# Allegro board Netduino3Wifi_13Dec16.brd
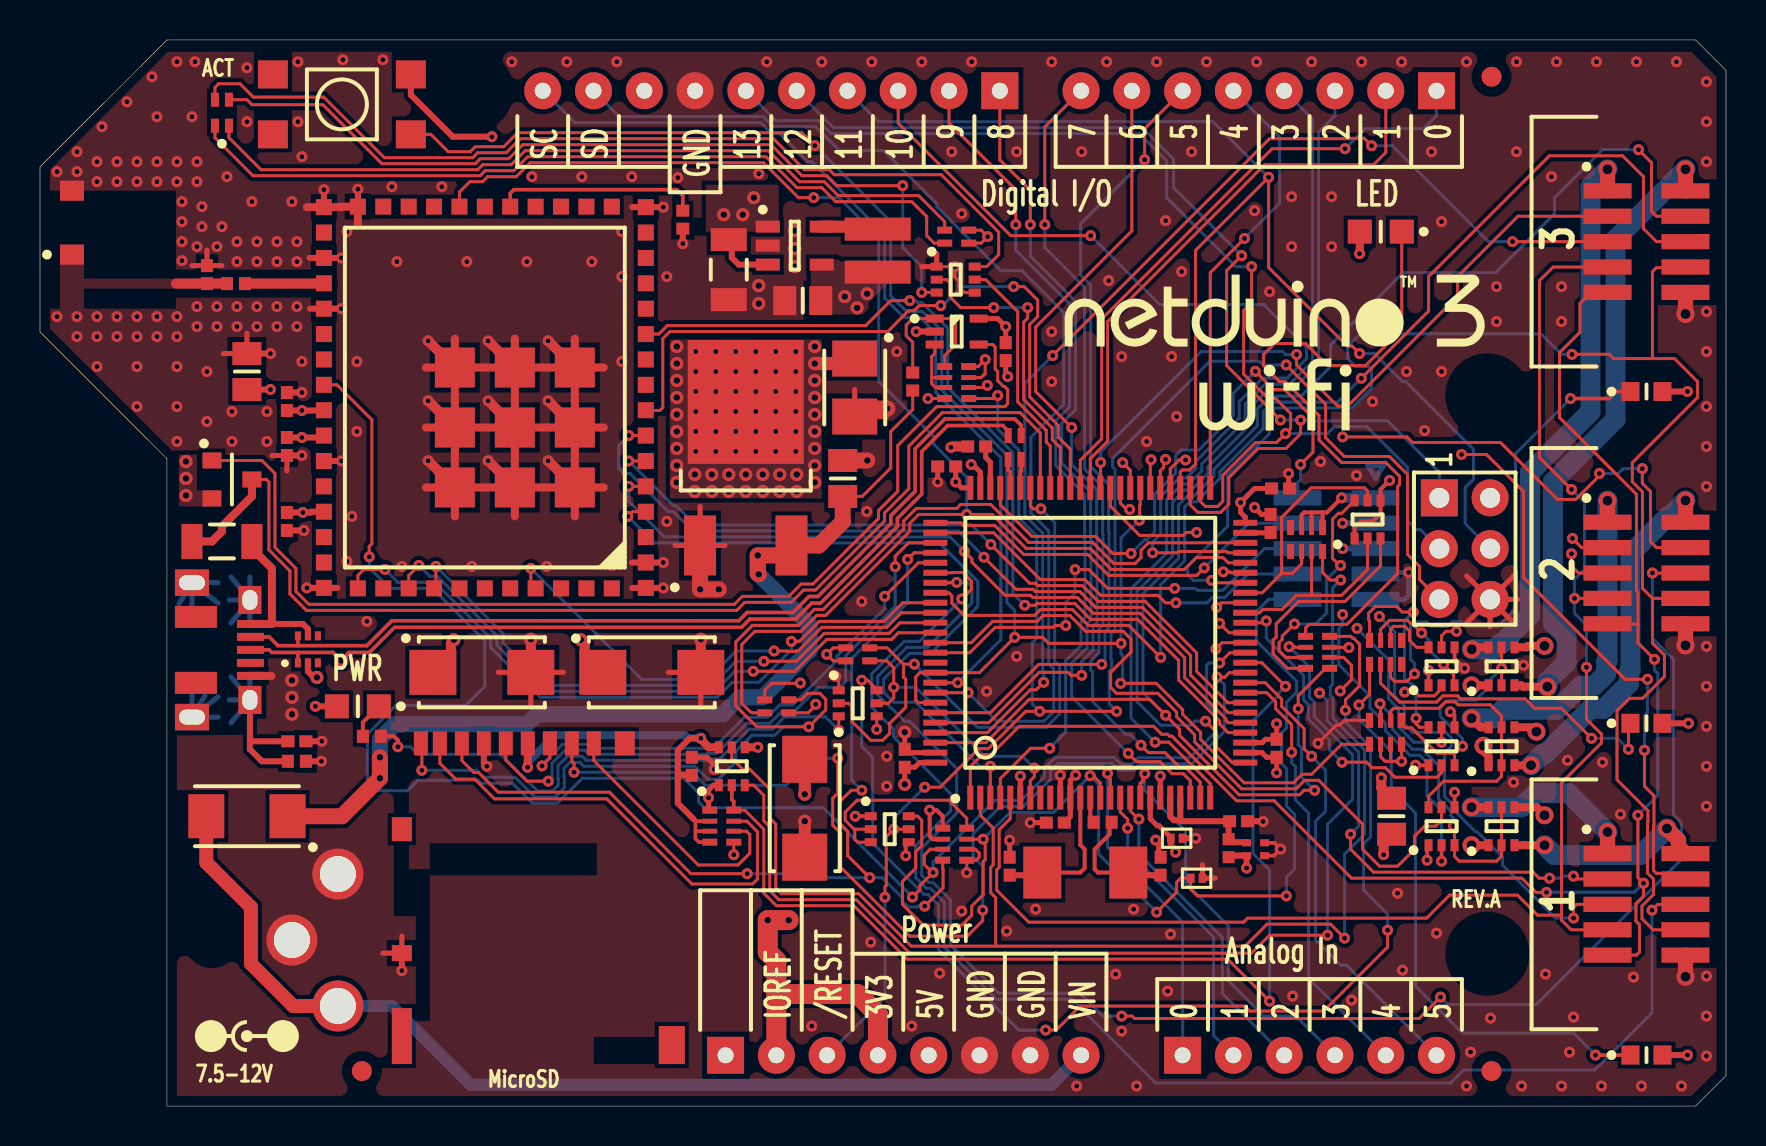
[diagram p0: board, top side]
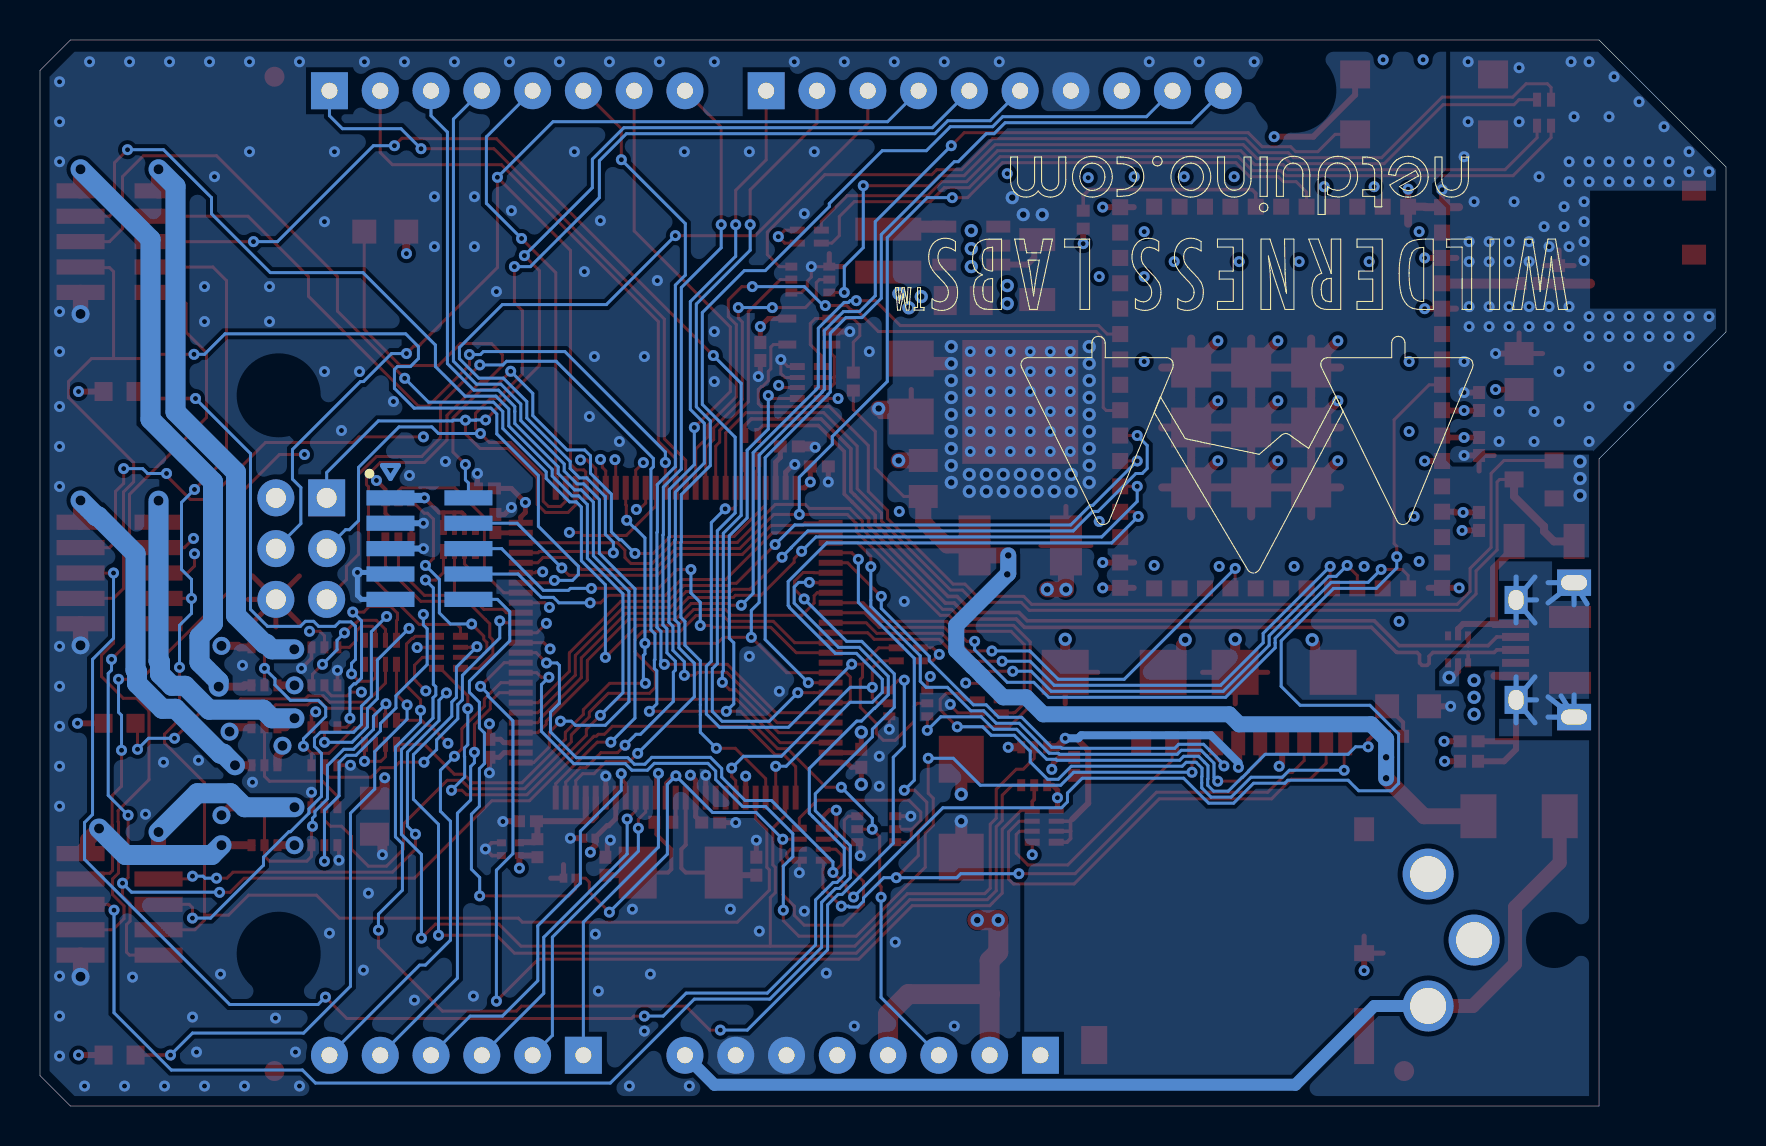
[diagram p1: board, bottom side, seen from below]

Outline 84.33 x 53.34 mm; copper layers: TOP, L2-GND, L3-PWR, BOTTOM. Coordinates in mm from the lower left corner of the outline.
Outline path: 0,46.99 0,38.73 6.35,32.38 6.35,0 82.8,0 84.33,1.52 84.33,51.82 82.8,53.34 6.35,53.34 0,46.99

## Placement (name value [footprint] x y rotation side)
C1  22uF  [CAPC3216X180N]  34.45 41.85 270 top
C2  10uF  [CAPC2012X125N]  40.15 31.4 90 top
C4  22uF  [CAPC2012X125N]  38.15 40.3 180 top
C5  0.1uF  [CAPC1005X55N]  59.95 14.25 0 top
C6  0.1uF  [CAPC1005X55N]  48.3 37.75 270 top
C7  1uF  [GNM1M2]  60.8 12.85 0 top
C9  0.1uF  [CAP-0201]  56.85 13.4 0 top
C10  0.1uF  [CAPC1005X55N]  50.78 14.18 180 top
C11  0.1uF  [CAPC1005X55N]  61.85 17.9 270 top
C12  0.1uF  [CAPC1005X55N]  62.05 30.9 0 top
C13  0.1uF  [CAPC1005X55N]  45.35 32 180 top
C14  0.1uF  [CAPC1005X55N]  43.25 17.4 90 top
C16  0.1uF  [CAPC1005X55N]  46.85 33 180 top
C17  2.2uF  [CAPC1005X55N]  61.55 29.15 90 top
C18  18pF  [CAPC1005X55N]  48.5 12 90 top
C19  18pF  [CAPC1005X55N]  56.05 12 90 top
C20  4.7nF  [CAPC1005X55N]  12.85 18.25 180 top
C21  100uF  [CAPMP6032X280N]  38.25 14.9 270 top
C22  0.1uF  [CAPC1005X55N]  32.6 17 90 top
C42  22uF  [CAPC2012X125N]  67.6 14.5 270 top
C43  47uF  [F931A476MBA]  40.75 35.95 270 top
C44  1pF  [CAPC1005X55N]  8.35 41.6 90 top
C47  22uF  [CAPC2012X125N]  10.35 36.75 90 top
C48  0.1uF  [CAPC1005X55N]  12.35 29.25 270 top
C49  0.1uF  [CAPC1005X55N]  12.35 35.25 90 top
C50  0.1uF  [CAPC1005X55N]  12.35 33 270 top
C51  100uF  [CAPMP6032X280N]  22.1 21.7 0 top
C52  100uF  [CAPMP6032X280N]  30.6 21.7 0 top
C53  0.1uF  [CAP-0201]  57.85 11.4 0 top
D1  WHITE  [LEDC2012X110N]  15.9 20 180 top
D2  BLUE  [LEDC2012X110N]  67.06 43.75 180 top
D3  SS15E-TP  [SS15-TP]  10.35 14.5 180 top
D4  -  [SP3003-04XTG]  13.4 22.85 90 top
D5  BLUE  [LEDC1608X80N]  80.35 2.55 0 top
D6  BLUE  [LEDC1608X80N]  80.35 19.15 0 top
D7  BLUE  [LEDC1608X80N]  80.35 35.75 0 top
D9  LTST-C295KGKSKT  [LTST-C295]  9.1 49.7 90 top
F1  MF-NSMF075-2  [RESC3216X100N]  9.1 28.25 180 top
F2  -  [FID_1-00_X_2-00]  16.1 1.75 0 top
F3  -  [FID_1-00_X_2-00]  72.6 1.75 0 top
F4  -  [FID_1-00_X_2-00]  72.6 51.5 0 top
J1  -  [ADC-043A-1]  14.9 8.31 90 top
J2  HDR100IMP08F-G-V-TH-BLUE  [HDR100IMP08F-G-V-TH]  69.85 50.8 180 top
J3  HDR100IMP08F-G-V-TH-BLUE  [HDR100IMP10F-G-V-TH]  48.01 50.8 180 top
J4  HDR100IMP08F-G-V-TH-BLUE  [HDR100IMP06F-G-V-TH]  57.15 2.54 0 top
J5  -  [DX4R005JJ2R1800]  6.35 22.82 270 top
J6  HDR100IMP08F-G-V-TH-BLUE  [HDR100IMP08F-G-V-TH]  34.29 2.54 0 top
J7  -  [67996-206HLF]  69.99 30.43 270 top
J8  -  [MINI_JTAG_SMD]  64.85 27.89 180 bottom
J9  DM3AT-SF-PEJM5  [DM3AT-SF-PEJ]  27.7 17.55 0 top
J10  HDR050IDC10MS2-G-V-SM-BLUE  [20021521-00010T1LF]  80.35 10.09 0 top
J11  HDR050IDC10MS2-G-V-SM-BLUE  [20021521-00010T1LF]  80.35 26.67 0 top
J12  HDR050IDC10MS2-G-V-SM-BLUE  [20021521-00010T1LF]  80.35 43.25 0 top
J13  2.45GHz Antenna  [AH316M245001-T]  1.6 44.2 90 top
L1  2.2uH  [LQH3NPN2R2NM0L]  41.9 42.8 270 top
L2  BEAD FERRITE/SM  [INDC1005X55N]  59.45 12.9 270 top
L3  3.6nH  [RESC1005X40AN]  9.8 41.15 180 top
MT1  -  [MTG320H420NP_720KO]  21.59 50.8 0 top
MT2  -  [MTG320H420NP_720KO]  72.39 35.56 0 top
MT3  -  [MTG320H420NP_720KO]  72.39 7.62 0 top
NOREF  -  []  0 38.73 90 top
NOREF#2  -  []  6.35 32.38 90 top
NOREF#3  -  []  0 46.99 0 top
NOREF#4  -  []  51.25 38 0 top
NOREF#5  -  []  10.35 3.5 0 top
NOREF#6  -  []  6.35 0 90 top
NOREF#7  -  []  6.35 53.34 0 top
NOREF#8  -  []  0 46.99 0 top
Q1  -  [MUN5215DW1T1G]  40.9 20.15 0 top
Q2  -  [MUN5215DW1T1G]  42.5 13.85 0 top
Q3  -  [NTR4101PT1G]  9.6 31.35 0 top
Q4  -  [NTJD4152PT1G]  34.6 17 90 top
Q5  -  [NTJD4152PT1G]  73.1 14 90 top
Q6  -  [MUN5215DW1T1G]  70.1 14 90 top
Q7  -  [NTJD4152PT1G]  73.1 18 90 top
Q8  -  [NTJD4152PT1G]  66.4 29.35 90 top
Q9  -  [NTJD4152PT1G]  73.1 22 90 top
Q10  -  [MUN5215DW1T1G]  70.1 18 90 top
Q11  -  [MUN5215DW1T1G]  70.1 22 90 top
Q12  -  [MUN5215DW1T1G]  45.8 41.35 0 top
R1  1K  [RESCAV50P80X160X60-8N]  63.9 22.7 0 top
R3  1.5K  [RESC1005X40AN]  16.6 18.5 0 top
R4  10K  [RESCAV50P80X160X60-8N]  45.85 36.2 0 top
R5  10K  [RESCAV50P80X160X60-8N]  45.75 13.1 0 top
R6  15.4K  [RESC1005X40AN]  43.65 36.25 90 top
R7  390  [RESC1005X40AN]  53.15 14.2 180 top
R8  10K  [EXB24V]  40.9 22.6 0 top
R9  22  [EXB24V]  48.75 32.95 270 top
R10  1M  [RESC1005X40AN]  12.85 17.25 180 top
R11  10K  [RESCAV50P80X160X60-8N]  34.1 14 0 top
R12  10K  [RESCAV50P80X160X60-8N]  67.3 18.7 90 top
R13  10K  [EXB24V]  36.85 20 0 top
R14  10K  [RESCAV50P80X160X60-8N]  63.35 28.35 270 top
R15  1K  [RESCAV50P80X160X60-8N]  67.3 22.7 90 top
R16  1.5K  [EXB24V]  45.85 43.5 180 top
R18  100K  [RESC1005X40AN]  32.15 44.35 270 top
SW1  -  [TSXH-2GL]  15.1 50.12 0 top
U1  LM3671MF-3.3/NOPB  [LM3671MF]  37.75 43.05 0 top
U2  -  [TLV1117-50IKVURG3]  35.3 28.05 90 top
U3  -  [LMV321IDCKR]  45.85 38.75 0 top
U4  STM32F427  [STM32F427VIT6]  52.53 23.18 90 top
U5  -  [CC3100MOD]  22.25 35.45 90 top
Y1  25.00MHz  [ABM7]  52.28 11.68 180 top

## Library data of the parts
C1 C2 C4-C6 C9-C14 C16-C22 C42-C44 C47-C53 = C
C7 = GNM1M2
D1 = LED_2
D2 D5-D7 = LED_1
D3 = D05AZ75_0
D4 = HEADER 6_0
D9 = LED_0
F1 = FUSE
F2-F4 MT1-MT3 = MOUNT_HOLE
J1 = HEADER 3
J2 J6 = HEADER 8
J3 = HEADER 10
J4 = HEADER 6
J5 = HEADER 11_0
J7 = HEADER 6_1
J8 J10-J12 = HEADER 10_2
J9 = HEADER 10_4
J13 = HEADER 2_0
L1 L3 = L
L2 = BEAD FERRITE/SM
Q1 Q2 Q12 = MUN5215DW1T1G_3
Q3 = NDF0610/TO_1
Q4 Q5 Q7-Q9 = NTJD4152PT1G
Q6 Q10 Q11 = MUN5215DW1T1G_0
R1 R4 R5 R11 R12 R14 R15 = RESCAV50P80X160X60-8N
R3 R6 R7 R10 R18 = R
R8 R9 R13 R16 = EXB24V
SW1 = SW PUSHBUTTON-SPST-2_0
U1 = HEADER 5_0
U2 = LM7805/TO_2
U3 = LMV321/SO
U4 = STM32F427_0
U5 = CC3100MOD_WIFI_MODULE_1
Y1 = CRYSTAL

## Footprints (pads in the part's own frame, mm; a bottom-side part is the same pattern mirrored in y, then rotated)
67996-206HLF
  rect 1.85x1.85 hole 1: 1(0,0)
  round 1.85 hole 1: 2(0,2.54) 3(2.54,0) 4(2.54,2.54) 5(5.08,0) 6(5.08,2.54)
20021521-00010T1LF
  rect 2.4x0.76 smd: 1(-1.95,2.54) 2(1.95,2.54) 3(-1.95,1.27) 4(1.95,1.27) 5(-1.95,0) 6(1.95,0) 7(-1.95,-1.27) 8(1.95,-1.27) 9(-1.95,-2.54) 10(1.95,-2.54)
ABM7
  rect 1.9x2.6 smd: 1(-2.15,0) 2(2.15,0)
ADC-043A-1
  round 0 hole 2.4 unplated: (0,6.3)
  round 2.55 hole 1.8: 1(-3.3,0) 2(0,2.3) 3(3.3,0)
AH316M245001-T
  rect 1x1.2 smd: 1(-1.6,0) 2(1.6,0)
CAP-0201
  rect 0.381x0.457 smd: 1(-0.292,0) 2(0.292,0)
CAPC1005X55N
  rect 0.65x0.6 smd: 1(-0.45,0) 2(0.45,0)
CAPC2012X125N
  rect 1.15x1.45 smd: 1(-0.9,0) 2(0.9,0)
CAPC3216X180N
  rect 1.15x1.8 smd: 1(-1.5,0) 2(1.5,0)
CAPMP6032X280N
  rect 2.35x2.25 smd: 1(-2.45,0) 2(2.45,0)
CC3100MOD
  rect 0.8x0.8 smd: 1(-9.525,-8.05) 2(-8.255,-8.05) 3(-6.985,-8.05) 4(-5.715,-8.05) 5(-4.445,-8.05) 6(-3.175,-8.05) 7(-1.905,-8.05) 8(-0.635,-8.05) 9(0.635,-8.05) 10(1.905,-8.05) 11(3.175,-8.05) 12(4.445,-8.05) 13(5.715,-8.05) 14(6.985,-8.05) 15(8.255,-8.05) 16(9.525,-8.05) 17(9.55,-6.35) 18(9.55,-5.08) 19(9.55,-3.81) 20(9.55,-2.54) 21(9.55,-1.27) 22(9.55,0) 23(9.55,1.27) 24(9.55,2.54) 25(9.55,3.81) 26(9.55,5.08) 27(9.55,6.35) 28(9.525,8.05) 29(8.255,8.05) 30(6.985,8.05) 31(5.715,8.05) 32(4.445,8.05) 33(3.175,8.05) 34(1.905,8.05) 35(0.635,8.05) 36(-0.635,8.05) 37(-1.905,8.05) 38(-3.175,8.05) 39(-4.445,8.05) 40(-5.715,8.05) 41(-6.985,8.05) 42(-8.255,8.05) 43(-9.525,8.05) 44(-9.55,6.35) 45(-9.55,5.08) 46(-9.55,3.81) 47(-9.55,2.54) 48(-9.55,1.27) 49(-9.55,0) 50(-9.55,-1.27) 51(-9.55,-2.54) 52(-9.55,-3.81) 53(-9.55,-5.08) 54(-9.55,-6.35)
  rect 2x2 smd: 55(-4.5,-4.5) 56(-1.5,-4.5) 57(1.5,-4.5) 58(-4.5,-1.5) 59(-1.5,-1.5) 60(1.5,-1.5) 61(-4.5,1.5) 62(-1.5,1.5) 63(1.5,1.5)
DM3AT-SF-PEJ
  rect 0.7x1.2 smd: 1(0,0.6) 2(-1.1,0.6) 3(-2.2,0.6) 4(-3.3,0.6) 5(-4.4,0.6) 6(-5.5,0.6) 7(-6.6,0.6) 8(-7.7,0.6) 9(-8.65,0.6)
  rect 1x0.8 smd: 10(-9.6,-9.9)
  rect 1x1.2 smd: 11(-9.6,-3.7) 14(1.55,0.6)
  rect 1x2.8 smd: 12(-9.6,-14.05)
  rect 1.3x1.9 smd: 13(3.9,-14.5)
DX4R005JJ2R1800
  rect 0.4x1.35 smd: 1(-1.3,4.175) 2(-0.65,4.175) 3(0,4.175) 4(0.65,4.175) 5(1.3,4.175)
  rect 1.4x1.15 hole 1x0.75: 6(-2.5,4.15) 7(2.5,4.15)
  rect 1.325x1.7 hole 0.75x1.3: 8(-3.362,1.25) 11(3.362,1.25)
  rect 1.1x2.1 smd: 9(-1.65,1.45) 10(1.65,1.45)
EXB24V
  rect 0.75x0.35 smd: 1(-0.6,0.325) 2(-0.6,-0.325) 3(0.6,-0.325) 4(0.6,0.325)
F931A476MBA
  rect 1.8x2.25 smd: 1(-1.45,0) 2(1.45,0)
FID_1-00_X_2-00
  round 1 smd: 1(0,0)
GNM1M2
  rect 0.45x0.35 smd: 1(-0.45,0.32) 2(-0.45,-0.32) 3(0.45,-0.32) 4(0.45,0.32)
HDR100IMP06F-G-V-TH
  rect 1.85x1.85 hole 0.8: 1(0,0)
  round 1.85 hole 0.8: 2(2.54,0) 3(5.08,0) 4(7.62,0) 5(10.16,0) 6(12.7,0)
HDR100IMP08F-G-V-TH
  rect 1.85x1.85 hole 0.8: 1(0,0)
  round 1.85 hole 0.8: 2(2.54,0) 3(5.08,0) 4(7.62,0) 5(10.16,0) 6(12.7,0) 7(15.24,0) 8(17.78,0)
HDR100IMP10F-G-V-TH
  rect 1.85x1.85 hole 0.8: 1(0,0)
  round 1.85 hole 0.8: 2(2.54,0) 3(5.08,0) 4(7.62,0) 5(10.16,0) 6(12.7,0) 7(15.24,0) 8(17.78,0) 9(20.32,0) 10(22.86,0)
INDC1005X55N
  rect 0.6x0.6 smd: 1(-0.45,0) 2(0.45,0)
LEDC1608X80N
  rect 0.899x0.95 smd: A(0.8,0) C(-0.8,0)
LEDC2012X110N
  rect 1.2x1.2 smd: A(1.05,0) C(-1.05,0)
LM3671MF
  rect 1.2x0.6 smd: 1(-1.35,0.95) 2(-1.35,0) 3(-1.35,-0.95) 4(1.35,-0.95) 5(1.35,0.95)
LMV321IDCKR
  rect 0.9x0.4 smd: 1(-1.1,0.65) 2(-1.1,0) 3(-1.1,-0.65) 4(1.1,-0.65) 5(1.1,0.65)
LQH3NPN2R2NM0L
  rect 1.15x3.3 smd: 1(-1.075,0) 2(1.075,0)
LTST-C295
  rect 0.7x0.4 smd: 1(-0.65,0.35) 2(-0.65,-0.35) 3(0.65,0.35) 4(0.65,-0.35)
MINI_JTAG_SMD
  rect 2.4x0.76 smd: 1(-1.95,2.54) 2(1.95,2.54) 3(-1.95,1.27) 4(1.95,1.27) 5(-1.95,0) 6(1.95,0) 7(-1.95,-1.27) 8(1.95,-1.27) 9(-1.95,-2.54) 10(1.95,-2.54)
MTG320H420NP_720KO
  round 0 hole 3.2 unplated: (0,0)
MUN5215DW1T1G
  rect 0.6x0.4 smd: 1(-0.95,0.65) 2(-0.95,0) 3(-0.95,-0.65) 4(0.95,-0.65) 5(0.95,0) 6(0.95,0.65)
NTJD4152PT1G
  rect 0.6x0.4 smd: 1(-0.95,0.65) 2(-0.95,0) 3(-0.95,-0.65) 4(0.95,-0.65) 5(0.95,0) 6(0.95,0.65)
NTR4101PT1G
  rect 0.95x0.8 smd: 1(-1,0.95) 2(-1,-0.95) 3(1,0)
RESC1005X40AN
  rect 0.6x0.65 smd: 1(-0.45,0) 2(0.45,0)
RESC3216X100N
  rect 1.05x1.75 smd: 1(-1.5,0) 2(1.5,0)
RESCAV50P80X160X60-8N
  rect 0.75x0.35 smd: 1(-0.6,0.8) 4(-0.6,-0.8) 5(0.6,-0.8) 8(0.6,0.8)
  rect 0.75x0.25 smd: 2(-0.6,0.25) 3(-0.6,-0.25) 6(0.6,-0.25) 7(0.6,0.25)
SP3003-04XTG
  rect 0.45x0.3 smd: 1(-0.675,0.5) 2(-0.675,0) 3(-0.675,-0.5) 4(0.675,-0.5) 5(0.675,0) 6(0.675,0.5)
SS15-TP
  rect 1.8x2.2 smd: A(2.032,0) C(-2.032,0)
STM32F427VIT6
  rect 1.2x0.3 smd: 1(-7.75,6) 2(-7.75,5.5) 3(-7.75,5) 4(-7.75,4.5) 5(-7.75,4) 6(-7.75,3.5) 7(-7.75,3) 8(-7.75,2.5) 9(-7.75,2) 10(-7.75,1.5) 11(-7.75,1) 12(-7.75,0.5) 13(-7.75,0) 14(-7.75,-0.5) 15(-7.75,-1) 16(-7.75,-1.5) 17(-7.75,-2) 18(-7.75,-2.5) 19(-7.75,-3) 20(-7.75,-3.5) 21(-7.75,-4) 22(-7.75,-4.5) 23(-7.75,-5) 24(-7.75,-5.5) 25(-7.75,-6) 51(7.75,-6) 52(7.75,-5.5) 53(7.75,-5) 54(7.75,-4.5) 55(7.75,-4) 56(7.75,-3.5) 57(7.75,-3) 58(7.75,-2.5) 59(7.75,-2) 60(7.75,-1.5) 61(7.75,-1) 62(7.75,-0.5) 63(7.75,0) 64(7.75,0.5) 65(7.75,1) 66(7.75,1.5) 67(7.75,2) 68(7.75,2.5) 69(7.75,3) 70(7.75,3.5) 71(7.75,4) 72(7.75,4.5) 73(7.75,5) 74(7.75,5.5) 75(7.75,6)
  rect 0.3x1.2 smd: 26(-6,-7.75) 27(-5.5,-7.75) 28(-5,-7.75) 29(-4.5,-7.75) 30(-4,-7.75) 31(-3.5,-7.75) 32(-3,-7.75) 33(-2.5,-7.75) 34(-2,-7.75) 35(-1.5,-7.75) 36(-1,-7.75) 37(-0.5,-7.75) 38(0,-7.75) 39(0.5,-7.75) 40(1,-7.75) 41(1.5,-7.75) 42(2,-7.75) 43(2.5,-7.75) 44(3,-7.75) 45(3.5,-7.75) 46(4,-7.75) 47(4.5,-7.75) 48(5,-7.75) 49(5.5,-7.75) 50(6,-7.75) 76(6,7.75) 77(5.5,7.75) 78(5,7.75) 79(4.5,7.75) 80(4,7.75) 81(3.5,7.75) 82(3,7.75) 83(2.5,7.75) 84(2,7.75) 85(1.5,7.75) 86(1,7.75) 87(0.5,7.75) 88(0,7.75) 89(-0.5,7.75) 90(-1,7.75) 91(-1.5,7.75) 92(-2,7.75) 93(-2.5,7.75) 94(-3,7.75) 95(-3.5,7.75) 96(-4,7.75) 97(-4.5,7.75) 98(-5,7.75) 99(-5.5,7.75) 100(-6,7.75)
TLV1117-50IKVURG3
  rect 3x1.6 smd: 1(0,2.286) 3(0,-2.286)
  rect 6.2x5.8 smd: 4(7.18,0)
TSXH-2GL
  rect 1.5x1.4 smd: 1(-3.45,1.5) 2(3.45,1.5) 3(-3.45,-1.5) 4(3.45,-1.5)

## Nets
3V3_GOPORT1: J10.1(3V3) Q5.6(DRAIN)
3V3_GOPORT2: J11.1(3V3) Q7.6(DRAIN)
3V3_GOPORT3: J12.1(3V3) Q9.6(DRAIN)
5V_GOPORT1: J10.2(5V) Q5.3(DRAIN)
5V_GOPORT2: J11.2(5V) Q7.3(DRAIN)
5V_GOPORT3: J12.2(5V) Q9.3(DRAIN)
+3.3V: C4.1 C7.2(1) C9.1 C10.1 C11.1 C12.1 C13.1 C14.1 C21.1 C42.1 C47.1 C48.1 C49.1 C50.1 C51.1 C52.1 J6.2 J6.4 J8.1(VCC) L1.2 L2.2 Q4.1(SOURCE) Q4.4(SOURCE) Q5.1(SOURCE) Q7.1(SOURCE) Q8.1(SOURCE) Q8.4(SOURCE) Q9.1(SOURCE) R4.4(1) R5.1 R5.2(1) R8.1 R8.2(1) R11.1 R13.1 R14.1 R14.2(1) R14.3(1) R16.1 R16.2(1) SW1.2 U1.4(FB) U4.6(VBAT) U4.11(VDD1) U4.19(VDD2) U4.28(VDD3) U4.50(VDD4) U4.75(VDD5) U4.100(VDD6) U5.36(VBAT_IN1) U5.37(VBAT_IN2) U5.40(VBAT_IN3)
+3V3_MICROSD: C22.1 J9.4(VDD) Q4.6(DRAIN) R11.2(1) R11.3(1) R11.4(1)
+5.0V: C1.1 C6.1 C43.1 D1.A(ANODE) D2.A(ANODE) D5.A(ANODE) D6.A(ANODE) D7.A(ANODE) J6.5 J7.2(VTG) Q3.2(SOURCE) Q5.4(SOURCE) Q7.4(SOURCE) Q9.4(SOURCE) R4.6(2) R12.2(1) R12.3(1) R12.4(1) U1.1(VIN) U1.3(EN) U2.4(VOUT) U3.5(+VCC)
+VIN: D3.A(1) J1.1 J6.8
+VIN_PROTECTED: C2.1 D3.C(2) R6.1 U2.3(VIN)
GND: C1.2 C2.2 C4.2 C5.2 C6.2 C7.3 C7.4(3) C9.2 C10.2 C11.2 C12.2 C13.2 C14.2 C16.2 C17.2 C18.2 C19.2 C20.1 C21.2 C22.2 C42.2 C43.2 C44.1 C44.2 C47.2 C48.2 C49.2 C50.2 C51.2 C52.2 C53.2 J1.2 J1.3 J3.7 J5.5(GND) J6.6 J6.7 J7.6(GND) J8.3(GND1) J8.5(GND2) J8.7(GND3) J8.9(GND4) J9.6(VSS) J9.10(SW_GND) J10.10(GND) J11.10(GND) J12.10(GND) J13.1 J13.2 L3.2 Q1.1(E) Q1.4(E) Q2.1(E) Q2.4(E) Q6.1(E) Q6.4(E) Q10.1(E) Q10.4(E) Q11.1(E) Q11.4(E) Q12.1(E) Q12.4(E) R4.7(2) R4.8(2) R5.5(2) R5.6(2) R10.1 R11.5(2) R12.8(2) R13.3(2) R18.2 U1.2(GND) U2.1(GND) U3.2(-VCC) U4.10(VSS1) U4.20(VSSA) U4.27(VSS2) U4.74(VSS3) U4.99(VSS4) U5.1(GND1) U5.2(GND2) U5.16(GND3) U5.27(GND4) U5.28(GND18) U5.30(GND5) U5.32(GND6) U5.38(GND7) U5.43(GND8) U5.55(GND9) U5.56(GND10) U5.57(GND11) U5.58(GND12) U5.59(GND13) U5.60(GND14) U5.61(GND15) U5.62(GND16) U5.63(GND17)
VIN_COMP_LOGIC: Q3.1(GATE) U3.4(OUT)
VIN_REF: R4.2(1) R4.3(1) U3.3(-VIN)
/CC_CS: U4.65(PC8) U5.8(SPI_CS)
/CC_HIB: U4.3(PE4) U5.4(NHIB)
/CC_RESET: R5.3(1) U4.37(PB2) U5.35(RESRT_N)
/ENABLE_UART_TX_PULLUP_GOPORT1: Q4.5(GATE) R14.8(2) U4.2(PE3)
/ENABLE_UART_TX_PULLUP_GOPORT2: Q8.2(GATE) R14.7(2) U4.41(PE10)
/ENABLE_UART_TX_PULLUP_GOPORT3: Q8.5(GATE) R14.6(2) U4.43(PE12)
/EXTERNAL_RESET: J6.3 J7.5(R\E\S\E\T\) Q2.5(B) R4.5(2)
/INT_GOPORT1: J10.3(GIPO) U4.60(PD13)
/INT_GOPORT2: J11.3(GIPO) U4.61(PD14)
/INT_GOPORT3: J12.3(GIPO) U4.62(PD15)
/MICRO_SD_CARD_INSERTED: J9.9(C\A\R\D\_\I\N\_\S\W\) R13.4(2) U4.48(PB11)
/MICROSD_CS: J9.2(C\S\) U4.35(PB0)
/PWR_CTRL_GOPORT1: Q5.2(GATE) Q5.5(GATE) Q6.3(C) R12.7(2)
/PWR_CTRL_GOPORT2: Q6.6(C) Q7.2(GATE) Q7.5(GATE) R12.6(2)
/PWR_CTRL_GOPORT3: Q9.2(GATE) Q9.5(GATE) Q10.3(C) R12.5(2)
/PWR_CTRL_MICROSD: Q4.2(GATE) R11.8(2) U4.36(PB1)
/RESET_MCU: C53.1 J8.10(NRST) Q2.6(C) R5.7(2) U4.14(NRST)
/SPI_CS_GOPORT1: J10.6(SPI_CS) U4.81(PD0)
/SPI_CS_GOPORT2: J11.6(SPI_CS) U4.82(PD1)
/SPI_CS_GOPORT3: J12.6(SPI_CS) U4.83(PD2)
A0: J4.1 U4.15(PC0)
A1: J4.2 U4.16(PC1)
A2: J4.3 U4.17(PC2)
A3: J4.4 U4.18(PC3)
A4: J4.5 U4.33(PC4)
A5: J4.6 U4.34(PC5)
CC_CTS: U4.85(PD4) U5.51(UART1_CTS)
CC_IRQ: U4.29(PA4) U5.11(I\RQ)
CC_MISO: U4.31(PA6) U5.7(SPI_DOUT)
CC_MOSI: U4.32(PA7) U5.6(SPI_DIN)
CC_RTS: U4.84(PD3) U5.44(UART1_RTS)
CC_RX: U4.86(PD5) U5.47(UART1_RX)
CC_SCK: U4.30(PA5) U5.5(SPI_CLK)
CC_TCXO_EN/SOP2: R13.2(1) U4.46(PE15) U5.23(SOP2)
CC_TX: U4.87(PD6) U5.46(UART1_TX)
D0: J2.1 U4.64(PC7)
D1: J2.2 U4.63(PC6)
D2: J2.3 U4.26(PA3)
D3: J2.4 U4.25(PA2)
D4: J2.5 U4.51(PB12)
D5: J2.6 U4.95(PB8)
D6: J2.7 U4.96(PB9)
D7: J2.8 U4.24(PA1)
D8: J3.1 U4.23(PA0)
D9: J3.2 U4.4(PE5)
D10: J3.3 U4.47(PB10)
D11: J3.4 J7.4(MOSI) U4.54(PB15)
D12: J3.5 J7.1(MISO) U4.53(PB14)
D13: J3.6 J7.3(SCK) U4.52(PB13)
JTCK: J8.4(JTCK) U4.76(PA14)
JTDI: J8.8(JTDI) U4.77(PA15)
JTDO: J8.6(JTDO) U4.89(PB3)
JTMS: J8.2(JTMS) U4.72(PA13)
LED: Q1.2(B) R8.4(2) U4.69(PA10)
LED_GOPORT1: Q10.2(B) U4.40(PE9)
LED_GOPORT2: Q11.5(B) U4.42(PE11)
LED_GOPORT3: Q11.2(B) U4.45(PE14)
LINK_LED: Q12.2(B) U4.66(PC9)
OTG_FS_DM: R9.4(2) U4.70(PA11)
OTG_FS_DP: R9.3(2) U4.71(PA12)
PWR_LED: Q1.5(B) R8.3(2) U4.7(PC13)
PWR_ON_GOPORT1: Q6.5(B) U4.88(PD7)
PWR_ON_GOPORT2: Q6.2(B) U4.57(PD10)
PWR_ON_GOPORT3: Q10.5(B) U4.59(PD12)
SCL: J3.10 U4.92(PB6)
SDA: J3.9 U4.93(PB7)
SPI3_MISO: J9.7(DO) R5.4(1) U4.79(PC11)
SPI3_MOSI: J9.3(DI) U4.80(PC12)
SPI3_SCK: J9.5(CLK) U4.78(PC10)
SPI4_MISO: J10.8(SPI_MISO) J11.8(SPI_MISO) J12.8(SPI_MISO) U4.44(PE13)
SPI4_MOSI: J10.7(SPI_MOSI) J11.7(SPI_MOSI) J12.7(SPI_MOSI) U4.5(PE6)
SPI4_SCK: J10.9(SPI_SCK) J11.9(SPI_SCK) J12.9(SPI_SCK) U4.1(PE2)
STATE_LED: Q12.5(B) U4.67(PA8)
SWITCH1: R12.1 SW1.4 U4.58(PD11) U4.91(PB5) U4.94(BOOT0)
USART3_RX_GOPORT1: J10.5(USART_RX) U4.56(PD9)
USART3_TX_GOPORT1: J10.4(USART_TX) R1.7(2) U4.55(PD8)
USART7_RX_GOPORT2: J11.5(USART_RX) U4.38(PE7)
USART7_TX_GOPORT2: J11.4(USART_TX) R1.6(2) U4.39(PE8)
USART8_RX_GOPORT3: J12.5(USART_RX) U4.97(PE0)
USART8_TX_GOPORT3: J12.4(USART_TX) R1.5(2) U4.98(PE1)
USB5V: D4.5(VCC) F1.1 J5.1(VBUS)
USB5V_F: F1.2 Q3.3(DRAIN) U4.68(PA9)
USB_D+: D4.1(I/O1) J5.3(D+) R9.2(1)
USB_D-: D4.6(I/O4) J5.2(D-) R9.1
VCAP_1: C17.1 U4.49(VCAP_1)
VCAP_2: C16.1 U4.73(VCAP_2)
N61621: C20.2 D4.2(GND) J5.6(CHS1) J5.7(CHS2) J5.8(CHS3) J5.11(CHS4) R10.2
N62667: R4.1 R6.2 U3.1(+VIN)
N62753: Q2.2(B) Q2.3(C) R5.8(2)
N62779: L1.1 U1.5(SW)
N62801: D2.C(CATHODE) R1.1
N62883: J9.1(NC) R11.6(2)
N62887: J9.8(RSV) R11.7(2)
N63081: C5.1 C7.1 L2.1 U4.21(VREF+) U4.22(VDDA)
N63113: C18.1 U4.12(PH0) Y1.2
N63117: R7.2 U4.13(PH1)
N63121: C19.1 R7.1 Y1.1
N74908: Q1.6(C) R1.8(2)
N77511: D1.C(CATHODE) R3.1
N77515: Q1.3(C) R3.2
N83970: D9.4(CATHODE_4) Q12.3(C)
N84209: D9.3(CATHODE_1) Q12.6(C)
N89038: L3.1 U5.31(RF_BG)
N89104: D9.2(ANODE_2) R16.3(2)
N89108: D9.1(ANODE_1) R16.4(2)
N89134: R18.1 U5.21(RESERVED#21)
N197515: Q10.6(C) R15.8(2)
N197535: D5.C(CATHODE) R15.1
N197921: Q11.3(C) R15.7(2)
N197949: D6.C(CATHODE) R15.2(1)
N198166: Q11.6(C) R15.6(2)
N198194: D7.C(CATHODE) R15.3(1)
N199051: Q4.3(DRAIN) R1.2(1)
N202411: Q8.6(DRAIN) R1.3(1)
N203046: Q8.3(DRAIN) R1.4(1)

Pads without a net: D4 3 4; F2 1; F3 1; F4 1; J3 8; J5 4 9 10; J6 1; J9 11 12 13 14; R14 4 5; R15 4 5; SW1 1 3; U4 8 9 90; U5 3 9 10 12 13 14 15 17 18 19 20 22 24 25 26 29 33 34 39 41 42 45 48 49 50 52 53 54

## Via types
v1: diameter 0.55, hole 0.25, TOP to BOTTOM, 553 vias
v2: diameter 0.9, hole 0.5, TOP to BOTTOM, 21 vias
v3: diameter 0.66, hole 0.33, TOP to BOTTOM, 68 vias

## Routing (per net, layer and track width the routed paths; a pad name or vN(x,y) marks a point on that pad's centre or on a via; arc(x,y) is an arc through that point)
3V3_GOPORT1: length 9.8
  TOP w0.4: Q5.6 v2(71.6,14.95)
  TOP w0.76: J10.1 v2(78.4,13.71)
  BOTTOM w1: v2(78.4,13.71) 76.46,15.65 74.79,15.65 74.09,14.95 v2(71.6,14.95)
3V3_GOPORT2: length 18.5
  TOP w0.4: Q7.6 72.05,18.95 v2(71.6,19.4)
  TOP w0.76: J11.1 v2(78.4,30.29)
  BOTTOM w1: v2(78.4,30.29) 78.4,22.28 78.32,22.21 78.32,21.62 77.73,21.02 77.06,21.02 75.87,19.83 73.16,19.83 72.72,19.4 v2(71.6,19.4)
3V3_GOPORT3: length 29.5
  TOP w0.4: v2(71.61,22.85) 71.71,22.95 Q9.6
  TOP w0.76: J12.1 v2(78.4,46.87)
  BOTTOM w1: v2(78.4,46.87) 77.55,46.02 77.55,34.73 74.52,31.71 74.52,24.55 73.1,23.13 73.01,23.13 72.73,22.85 v2(71.61,22.85)
5V_GOPORT1: length 10
  TOP w0.4: Q5.3 v2(75.25,13.05)
  TOP w0.76: v2(81.37,13.89) 81.95,13.31 81.95,12.98 J10.2
  BOTTOM w1: v2(75.25,13.05) 75.74,12.56 80.05,12.56 v2(81.37,13.89)
5V_GOPORT2: length 18.9
  TOP w0.4: Q7.3 v2(74.57,17.05)
  TOP w0.76: v2(82.3,30.3) J11.2
  BOTTOM w1: v2(74.57,17.05) 75.16,17.63 75.3,17.63 77.55,19.88 78.21,19.88 79.47,21.14 79.47,21.73 79.55,21.81 79.55,27.64 81.42,29.5 81.5,29.5 v2(82.3,30.3)
5V_GOPORT3: length 32.1
  TOP w0.4: Q9.3 74.09,21.05 74.16,20.98 v2(75.39,20.98)
  TOP w0.76: J12.2 v2(82.3,46.87)
  BOTTOM w1: v2(82.3,46.87) 78.8,43.37 78.8,34.36 75.67,31.23 75.67,24.16 76.35,23.48 76.35,22.2 75.39,21.24 v2(75.39,20.98)
+3.3V: length 79.7
  TOP w0.15: R8.2 39.68,22.27 v1(39.35,22.6) 39.68,22.93 R8.1 ; R13.1 36.25,20.8 36.6,21.15 38.05,21.15 38.05,21.17 v1(38.03,21.17) ; R16.1 47.08,43.17 v1(47.4,43.5) 47.08,43.83 R16.2 ; R4.4 v1(44.41,35.4)
  TOP w0.2: v1(67.5,31.3) 67.05,30.85 Q8.4 67.05,29.65 66.65,29.25 66.05,29.25 65.75,28.95 Q8.1 ; 64.15,29.7 R14.1 ; 64.15,29.7 63.6,29.7 ; 64.15,29.7 64.37,29.7 v1(65.1,30.43) ; R14.3 63.1,29.57 63.23,29.7 63.6,29.7 ; 63.6,29.7 R14.2 ; R5.2 44.65,13.35 44.5,13.5 v1(44.5,14.8) 44.85,14.8 45.15,14.5 R5.1
  TOP w0.25: v3(43.25,16.09) C14.1 43.75,16.95 43.98,17.18 U4.100 ; U4.75 46.09,30.93 v1(45.8,31.23) C13.1 ; R11.1 33.44,14.86 v1(33.44,15.43) 33.43,15.44 33.43,15.8 33.68,16.05 Q4.1 ; U4.28 61.13,18.18 61.3,18.35 C11.1 v1(61.85,19.12) ; C9.1 56.56,13.44 55.97,14.03 55.88,14.03 55.53,14.38 U4.19 ; v1(51.8,16.55) 51.79,16.55 51.78,16.55 51.53,16.3 U4.11 51.53,14.48 C10.1 ; C12.1 60.75,30.9 v1(60.05,30.2) 60.05,29.7 60.28,29.47 U4.50 ; U4.6 v1(49.03,16.51)
  TOP w0.3: v1(22.6,48.5) 20.64,48.5 18.55,50.59 SW1.2 ; C9.1 56.56,13.04 56.8,12.8 v1(56.8,12.7) ; U5.37 14.11,33.45 v1(13.1,33.45) C50.1 ; v1(60.35,11.9) C7.2 59.53,12.53 L2.2 ; U5.36 14.18,34.8 v1(13.1,34.8) C49.1 ; C48.1 v1(13.15,29.7) 13.55,29.7 13.59,29.73 U5.40 ; C47.1 v1(11.52,35.85)
  TOP w0.4: Q4.4 v1(35.9,17.95) ; v2(72.2,18.03) 72.2,17.75 72.45,17.5 Q7.1 ; Q5.1 v2(71.6,13.05) ; Q9.1 v2(71.6,21.05)
  TOP w0.5: v1(67.09,16.43) 67.09,15.91 C42.1 ; C52.1 27.25,22.6 27.25,23.1 27.05,23.3 v3(27.05,23.33) ; C51.1 20.55,22.6 20.55,23.15 20.7,23.3 v3(20.7,23.33)
  TOP w0.6: C21.1 v3(38.25,15.6)
  TOP w1: 36.83,5.6 J6.2 ; 36.83,5.6 40.9,5.6 41.91,4.59 J6.4 ; 36.83,5.6 36.83,7.27 36.4,7.7 v3(36.4,9.3) v3(37.45,9.3)
  BOTTOM w0.5: J8.1 v1(65.1,30.43)
  vias: v3(40.25,40.5) v3(40.87,39.94) v3(41.37,40.64)
+3V3_MICROSD: length 21
  TOP w0.18: 32.78,14.27 32.8,14.25 R11.2 ; 32.78,14.27 32.78,13.75 ; 32.78,14.27 32.7,14.35 ; R11.4 32.96,13.2 32.78,13.38 32.78,13.75 ; 32.78,13.75 R11.3
  TOP w0.3: v1(33.05,18.4) 32.5,18.4 31.9,17.8 31.9,16.55 ; 32.7,14.35 31.9,15.15 31.9,16.55 ; 31.9,16.55 C22.1
  TOP w0.4: J9.4 24.4,16.96 v1(24.39,16.95) ; v1(33.05,18.4) 33.05,18.35 33.45,17.95 Q4.6
  BOTTOM w0.4: v1(24.39,16.95) 24.39,17.18 25.76,18.55 32.25,18.55 32.4,18.4 v1(33.05,18.4)
+5.0V: length 28.3
  TOP w0.15: 67.55,17.25 v1(68.1,17.25) R12.4 ; 67.55,17.25 67.27,17.25 67.05,17.48 R12.2 ; 67.55,17.25 R12.3 ; R4.6 47.2,35.95 47.31,36.06 47.38,36.06 47.38,36.06 v1(47.38,36.06)
  TOP w0.18: C1.1 34.6,43.2
  TOP w0.25: C6.1 v1(48.3,39) 47.9,39.4 U3.5
  TOP w0.3: 34.6,43.2 34.6,42.45 34.95,42.1 U1.3 ; D6.A v1(82.45,19.15) ; D7.A v1(82.4,35.75) ; D5.A v1(82.4,2.55) ; D1.A v1(13.77,20)
  TOP w0.4: D2.A 66.01,42.66 v1(66,42.65) ; Q9.4 74.35,22.95 74.42,23.02 v2(75.25,23.02) ; v2(75.25,14.55) 74.85,14.95 Q5.4 ; v2(74.85,18.73) 74.85,18.83 74.72,18.95 Q7.4
  TOP w0.66: v3(38.75,37.15) 40.5,37.15 C43.1
  L3-PWR w0.254: J7.2 73.9,30.43 ; J7.2 73.7,29.26 ; J7.2 73.7,31.6 ; J7.2 72.53,31.8
  vias: v1(32.8,37.75) v1(32.8,36.75) v1(32.8,35.75) v1(32.8,34.75) v1(32.8,33.75) v1(32.8,32.75) v1(33.8,37.75) v1(33.8,36.75) v1(33.8,35.75) v1(33.8,34.75) v1(33.8,33.75) v1(33.8,32.75) v1(34.8,37.75) v1(34.8,36.75) v1(34.8,35.75) v1(34.8,34.75) v1(34.8,33.75) v1(34.8,32.75) v1(35.8,37.75) v1(35.8,36.75) v1(35.8,35.75) v1(35.8,34.75) v1(35.8,33.75) v1(35.8,32.75) v1(36.8,37.75) v1(36.8,36.75) v1(36.8,35.75) v1(36.8,34.75) v1(36.8,33.75) v1(36.8,32.75) v1(37.8,37.75) v1(37.8,36.75) v1(37.8,35.75) v1(37.8,34.75) v1(37.8,33.75) v1(37.8,32.75) v3(7.3,32.25) v3(7.3,31.4) v3(7.3,30.55) v3(31.85,38) v3(31.85,37.15) v3(31.85,36.3) v3(31.85,35.45) v3(31.85,34.6) v3(31.85,33.75) v3(31.85,32.9) v3(31.85,32.05) v3(31.85,31.2) v3(32.75,31.6) v3(32.75,30.75) v3(33.6,31.6) v3(33.6,30.75) v3(34.2,44.6) v3(34.45,31.6) v3(34.45,30.75) v3(35.15,44.6) v3(35.3,31.6) v3(35.3,30.75) v3(35.7,45.45) v3(36.15,31.6) v3(36.15,30.75) v3(37,31.6) v3(37,30.75) v3(37.85,31.6) v3(37.85,30.75) v3(38.75,38) v3(38.75,36.3) v3(38.75,35.45) v3(38.75,34.6) v3(38.75,33.75) v3(38.75,32.9) v3(38.75,32.05) v3(38.75,31.2)
+VIN: length 52.9
  TOP w0.7: D3.A 8.32,12.18 10.55,9.95 10.55,7.12 12.66,5.01 J1.1
  BOTTOM w0.6: J1.1 17.59,5.01 21.54,1.06 50.59,1.06 J6.8
+VIN_PROTECTED: length 52.1
  TOP w0.15: R6.1 43.65,34.85 42.55,33.75 42.55,31.93 41.12,30.5 C2.1
  TOP w0.8: v3(17,17.45) v3(17,16.4) 15.1,14.5 D3.C ; C2.1 40.15,29.24 38.96,28.05 U2.3 37.09,27.55 v3(35.9,27.55) 35.9,26.65 v3(35.95,26.6)
  BOTTOM w0.8: v3(17,16.4) v3(17,17.45) 17,18.36 17.74,19.1 24.35,19.1 24.85,19.6 34.15,19.6 35,20.45 36.15,20.45 37.2,21.5 37.2,21.51 37.69,21.99 37.69,21.99 38.5,22.8 38.5,24.05 v3(35.95,26.6) 35.9,26.65 v3(35.9,27.55)
GND: length 203.3
  TOP w0.15: v1(63.92,18.15) 64.83,19.05 65,19.05 65.25,19.3 R12.8 ; R4.8 46.93,37 v1(47.27,37.35) 47.27,36.65 47.18,36.56 47.18,36.56 47.07,36.45 R4.7 ; R5.6 46.78,12.85 46.98,12.65 46.98,12.45 46.83,12.3 R5.5 v1(46.35,11.68) ; R11.5 v1(34.7,12.57) ; Q1.4 v1(41.85,18.85) ; v1(38.8,20.1) 38.8,20.05 38.43,19.68 R13.3 ; v1(39.8,21.49) 39.8,21.4 39.95,21.25 Q1.1 ; Q12.4 46.25,40.7 45.95,41 45.95,41.27 45.75,41.48 v1(45.75,42) Q12.1
  TOP w0.18: Q6.1 69.38,12.98 v1(69.38,12.3) ; Q10.1 v1(68.8,17.05) ; C7.4 61.74,13.17 v1(62.05,12.86) 61.72,12.53 C7.3 ; v1(71.25,21.9) 70.75,22.4 Q11.4 ; Q10.4 70.75,19.55 70.57,19.73 v1(70.54,19.73) ; Q6.4 v1(70.75,15.7) ; v1(69.45,21.8) Q11.1
  TOP w0.2: Q2.4 43.3,13.05 v1(43.3,12.52) ; Q2.1 v1(40.77,14.5)
  TOP w0.25: C17.2 61.1,29.6 v1(60.75,29.95) ; C22.2 33.35,17.45 33.65,17.15 33.65,16.92 v1(33.72,16.85) ; v1(46.58,32.1) 46.65,32.1 47.03,31.72 U4.74 ; U4.10 v1(51.03,16.55) ; U4.27 61.12,17.68 61.35,17.45 C11.2 v1(61.85,16.68) ; C10.2 v1(49.53,14.18) ; C12.2 62.45,30.95 v1(62.45,31.65) ; C6.2 48.3,36.6 v1(48.4,36.5) ; v1(55.8,13.31) 55.95,13.16 55.95,12.55 C19.2 ; U4.20 v1(56.03,16.51) ; C18.2 v1(48.5,13.3) ; C13.2 v1(44.9,31.23) ; v3(43.25,18.71) C14.2 43.42,17.68 U4.99
  TOP w0.254: 72.53,23.98 J7.6 ; J7.6 71.36,26.52 ; J7.6 73.7,26.52 ; J7.6 71.36,24.18 ; J7.6 73.7,24.18 ; J7.6 73.9,25.35 ; 22.93,21.7 C51.2 ; C51.2 24.55,20.13 ; C51.2 26.17,21.7 ; 44.85,42.65 Q12.1 44.1,42 ; U2.1 34.26,28.05 ; U2.1 33.01,30 ; U2.1 31.76,28.05 ; 58.78,11.4 C53.2 58.14,12.08 ; 31.43,21.7 C52.2 33.05,20.13 ; 40.75,35.85 C43.2 42.32,34.5 ; 9.18,37.65 C47.2 10.35,38.67 ; C44.2 9.1,42.05 ; C44.2 8.35,42.82 ; C44.2 7.6,42.05 ; 11.6,32.55 C50.2 12.35,31.78 ; 17.15,7.65 J9.10 18.1,8.5
  TOP w0.3: v1(31.17,44.98) U5.16 29.62,44.98 ; 29.62,25.93 v1(31.17,25.93) ; 13.48,42.44 U5.30 v1(15.07,42.44) ; U5.27 v1(15.9,45.88) ; U3.2 v1(43.83,38.75) ; C48.2 v1(13.2,28.8) ; v1(22.35,17) 22.2,17.15 J9.6 ; C49.2 v1(13.1,35.7) ; 29.6,27.2 U5.2 v1(31.17,27.2) ; v1(15.07,39.9) U5.32 13.5,39.9 ; C50.2 v1(13.1,32.55) ; R18.2 v1(32.15,43.15) ; R10.1 v1(14.07,17.25) ; C9.2 v1(57.8,13.4) ; U5.28 v1(14.2,45.85) ; C5.2 61.16,14.25 v1(61.18,14.24) ; U5.38 v1(15.07,32.27) ; C47.2 v1(11.52,37.65) ; 14.88,25.93 v1(13.35,25.93) ; C20.1 v1(14.1,18.25) ; J9.10 v1(18.1,6.78)
  TOP w0.4: 25.3,33.95 U5.56 ; U5.56 28.2,33.95 ; U5.56 26.75,32.5 ; U5.56 26.75,35.4 ; 20.75,35.5 U5.63 ; U5.63 20.75,38.4 ; U5.63 22.2,36.95 ; U5.63 19.3,36.95 ; U5.57 26.75,38.4 ; U5.57 26.75,35.5 ; U5.57 28.2,36.95 ; U5.57 25.3,36.95 ; U5.61 20.75,32.4 ; U5.61 19.3,30.95 ; U5.61 22.2,30.95 ; U5.61 20.75,29.5 ; 15.9,44.15 U5.27 15.05,45 ; 26.75,29.5 U5.55 ; U5.55 28.2,30.95 ; U5.55 26.75,32.4 ; U5.55 25.3,30.95 ; 19.3,33.95 U5.62 ; U5.62 20.75,35.4 ; U5.62 20.75,32.5 ; U5.62 22.2,33.95 ; 22.3,33.95 U5.59 ; U5.59 25.2,33.95 ; U5.59 23.75,32.5 ; U5.59 23.75,35.4 ; U5.58 23.75,32.4 ; U5.58 22.3,30.95 ; U5.58 23.75,29.5 ; U5.58 25.2,30.95 ; 15.05,44.98 U5.28 13.35,44.98 ; 23.75,35.5 U5.60 ; U5.60 25.2,36.95 ; U5.60 23.75,38.4 ; U5.60 22.3,36.95 ; J5.5 11.58,21.52
  TOP w0.5: U5.59 v1(22.41,35.29) ; v1(67.2,12.57) 67.2,13.2 C42.2 ; U5.55 v1(25.41,32.29) ; U5.60 v1(22.41,38.29) ; C51.2 v3(24.55,23.36) ; U5.63 v1(19.41,38.29) ; U5.57 v1(25.41,38.29) ; C52.2 v3(33.05,23.36) ; L3.2 C44.1 6.8,41.15 ; U5.62 v1(19.41,35.29) ; C16.2 45.64,33 45.6,32.96 v1(45.56,32.96) ; U5.58 v1(22.41,32.29) ; U5.61 v1(19.41,32.29) ; U5.56 v1(25.41,35.29)
  TOP w0.6: C21.2 v3(38.25,14.25)
  TOP w0.76: J11.10 v2(82.3,23.05) ; J12.10 v2(82.3,39.63) ; J10.10 v2(82.3,6.47)
  TOP w0.8: C43.2 41.15,34.9 v3(42.38,34.9) ; v3(41.38,32.3) C2.2 ; U2.1 v3(33.01,25.85) v3(33.95,25.85)
  L2-GND w0.254: J7.6 73.9,25.35 ; J7.6 73.7,24.18 ; J7.6 71.36,26.52 ; J7.6 73.7,26.52
  BOTTOM w0.25: J8.9 68.25,25.35 68.45,25.55 v1(68.45,26.7) 66.88,26.7 J8.7
  BOTTOM w0.3: J8.3 v1(65.15,29.16) ; J8.5 v1(65.15,27.89)
  vias: v1(0.85,46.75) v1(0.85,39.5) v1(1.85,47.75) v1(1.85,46.75) v1(1.85,39.5) v1(1.85,38.5) v1(2.85,47.25) v1(2.85,46.25) v1(2.85,39.5) v1(2.85,38.5) v1(2.85,37) v1(3.1,49) v1(3.85,47.25) v1(3.85,46.25) v1(3.85,39.5) v1(3.85,38.5) v1(4.35,50.25) v1(4.85,47.25) v1(4.85,46.25) v1(4.85,39.5) v1(4.85,38.5) v1(4.85,37) v1(4.85,35) v1(5.6,51.5) v1(5.85,49.5) v1(5.85,47.25) v1(5.85,46.25) v1(5.85,39.5) v1(5.85,38.5) v1(6.85,52.25) v1(6.85,47.25) v1(6.85,46.25) v1(6.85,39.5) v1(6.85,38.5) v1(6.85,37) v1(6.85,35) v1(6.85,33.25) v1(7.1,45.25) v1(7.1,44.25) v1(7.1,43.25) v1(7.1,42.3) v1(7.6,49.5) v1(7.75,52.25) v1(7.85,47.25) v1(7.85,46.25) v1(7.85,43) v1(7.85,40) v1(7.85,39) v1(8.1,45) v1(8.1,44) v1(8.35,36.75) v1(8.35,34.25) v1(8.85,43) v1(8.85,40) v1(8.85,39) v1(9.1,44) v1(9.35,46.5) v1(9.6,34.75) v1(9.6,33.25) v1(9.85,43.25) v1(9.85,42.25) v1(9.85,40) v1(9.85,39) v1(10.35,51.95) v1(10.35,49.25) v1(10.6,45.25) v1(10.85,43.25) v1(10.85,42.25) v1(10.85,40) v1(10.85,39) v1(11.35,34.75) v1(11.35,33.25) v1(11.85,43.25) v1(11.85,42.25) v1(11.85,40) v1(11.85,39) v1(12.6,45.25) v1(12.9,52.25) v1(12.9,49.25) v1(12.85,43.25) v1(12.85,42.25) v1(12.85,40) v1(12.85,39) v1(13.1,47.5) v1(13.1,37.25) v1(15.15,52.35) v1(15.35,43.75) v1(15.35,27.25) v1(15.6,29.5) v1(15.85,37.25) v1(15.85,33.75) v1(16.35,24.25) v1(17.15,52.35) v1(17.6,46) v1(17.85,42.25) v1(18.1,27) v1(20.1,46) v1(21.35,42.25) v1(21.6,27) v1(23.6,52.25) v1(24.35,42.25) v1(24.6,46.5) v1(25.35,27) v1(26.35,52.25) v1(27.1,46.5) v1(27.6,42.25) v1(28.6,27.05) v1(28.85,52.25) v1(29.1,43.75) v1(29.1,41.5) v1(29.1,37.25) v1(29.6,46.5) v1(31.35,41.5) v1(31.35,29.25) v1(31.9,46.45) v1(35.95,46.65) v1(36.35,52.25) v1(38.6,4) v1(39.1,52.25) v1(41.1,25.25) v1(41.35,29.75) v1(41.6,52.25) v1(41.55,8.2) v1(42.35,17.5) v1(42.35,16) v1(42.85,37.75) v1(43.6,4) v1(44.1,52.25) v1(45,6.65) v1(45.6,47.75) v1(46.1,44.65) v1(46.1,9.75) v1(46.6,52.25) v1(47.35,20.75) v1(48.35,8.75) v1(48.85,47.75) v1(48.85,22.5) v1(49.8,9.85) v1(50.6,52.25) v1(50.6,38.75) v1(50.6,36.25) v1(51.85,1) v1(52.1,47.75) v1(53.35,52.25) v1(53.45,41.3) v1(53.8,6.6) v1(54.1,37.5) v1(54.1,3.75) v1(54.7,9.85) v1(54.85,1) v1(55.35,33.25) v1(55.85,52.25) v1(56.3,44.3) v1(56.4,5.75) v1(56.6,37.5) v1(56.55,8.6) v1(56.85,34.5) v1(57.1,41.75) v1(57.6,47.75) v1(58.35,52.25) v1(60.75,44.8) v1(60.85,52.25) v1(61.5,40.75) v1(62.6,45.5) v1(62.6,43) v1(62.65,5.5) v1(63.6,52.25) v1(64.05,32.25) v1(64.6,45.5) v1(64.6,43) v1(65.6,5.3) v1(65.85,31.55) v1(66.1,52.25) v1(66.65,35.25) v1(67.9,10.65) v1(68.1,52.25) v1(68.15,6.8) v1(68.35,36.75) v1(69.25,33.8) v1(69.6,47.75) v1(69.85,8.65) v1(70.1,44.25) v1(70.1,36.75) v1(71.35,52.25) v1(71.35,1) v1(71.55,2.7) v1(72.55,4.4) v1(72.85,41) v1(72.85,39.25) v1(73.7,16.2) v1(73.85,52.25) v1(73.85,47.75) v1(74.2,22.05) v1(74.1,1) v1(75.3,6.6) v1(75.6,46.5) v1(75.85,52.25) v1(76.1,41) v1(76.1,39.25) v1(76.1,1) v1(76.4,17.3) v1(76.5,2.7) v1(76.7,4.45) v1(77.85,52.25) v1(78.15,17.2) v1(78.1,1) v1(79.05,14.6) v1(79.7,6.45) v1(79.85,52.25) v1(80.1,1) v1(81.85,52.25) v1(82.1,1) v1(83.35,51.25) v1(83.35,49.25) v1(83.35,47.25) v1(83.35,39.75) v1(83.35,37.75) v1(83.35,35) v1(83.35,33) v1(83.35,31) v1(83.35,23) v1(83.35,21) v1(83.35,19) v1(83.35,17) v1(83.35,15) v1(83.35,6.5) v1(83.35,4.5) v1(83.35,2.5) v3(12.6,21.3) v3(12.6,20.45) v3(12.6,19.6) v3(35.95,41.05) v3(35.95,40.15) v3(37.75,43.8) v3(37.75,42.9) v3(37.75,42)
VIN_COMP_LOGIC: length 55.4
  TOP w0.15: Q3.1 11.1,32.3 11.75,31.65 11.75,27.95 12.8,26.9 12.8,25.75 13.45,25.1 34.73,25.1 35.13,25.5 37.45,25.5 38.07,26.12 38.66,26.12 41.94,29.4 41.94,29.8 42.9,30.76 42.9,33.05 44.84,34.99 48.25,34.99 48.4,35.15 48.4,35.85 48.25,36 48.19,36 47.9,36.29 47.9,36.76 47.77,36.88 47.77,37.98 47.65,38.1 U3.4
VIN_REF: length 3.4
  TOP w0.15: U3.3 44.75,37.65 44.6,37.5 44.6,36.5 ; 44.6,36.5 44.6,36.14 44.79,35.95 R4.3 ; 44.6,36.5 44.65,36.45 R4.2
/CC_CS: length 35
  TOP w0.15: v1(45.05,40.05) 43.98,40.05 43.76,39.84 43.75,39.84 43.71,39.8 43.44,39.8 42.4,38.75 31.5,38.75 31.15,38.4 31.15,34.95 31,34.8 30.31,34.8 U5.8 ; U4.65 51.53,32.87 50.93,33.47 50.93,34.05 49.5,35.48 49.5,39.1 49.9,39.5 49.9,40.33 49.23,41 v1(48.7,41)
  BOTTOM w0.15: v1(48.7,41) 46.1,41 45.05,39.95 v1(45.05,40.05)
/CC_HIB: length 36.4
  TOP w0.15: v1(47.53,17) U4.3 ; U5.4 29.63,29.73 v1(29.4,29.5)
  BOTTOM w0.15: v1(29.4,29.5) 30.73,28.18 44.98,28.18 46.91,26.24 46.91,25.04 46.85,24.98 46.85,24.95 44.55,22.65 43.5,22.65 42.2,21.35 42.2,20.7 42.7,20.2 43.81,20.2 47.01,17 v1(47.53,17)
/CC_RESET: length 88.4
  TOP w0.15: U5.35 14.85,36.09 16.6,34.34 16.6,28.14 16.47,28.01 v1(16.47,27.48) ; v1(59,22.17) 59.51,22.68 U4.37 ; v1(43.64,10.46) 44.01,10.83 44.01,11.03 v1(44.67,11.69) 44.67,11.78 44.6,11.78 44.6,11.71 44.23,12.08 44.23,12.55 44.52,12.85 R5.3
  BOTTOM w0.15: v1(16.47,27.48) 16.47,26.93 17.49,25.9 19.63,25.9 22.25,23.28 22.25,21 21.3,20.05 17.81,20.05 16.38,18.61 16.38,16.14 16.74,15.78 18.38,15.78 18.9,16.3 21.92,16.3 22.07,16.15 23.63,16.15 24.63,15.15 25.88,15.15 27.12,16.4 32.2,16.4 32.94,15.66 32.94,15.22 33.23,14.93 39.17,14.93 v1(43.64,10.46) ; v1(59,22.17) 58.47,22.17 58.35,22.05 58.35,20.15 58.8,19.7 58.8,18.72 57.5,17.43 54.93,17.43 54.6,17.1 54.07,17.1 53.73,17.45 50.8,17.45 50.23,16.88 50.23,16.46 49.06,15.29 47.74,15.29 44.67,12.21 v1(44.67,11.69)
/ENABLE_UART_TX_PULLUP_GOPORT1: length 67.8
  TOP w0.15: 47.8,8 43.57,8 40.95,10.62 37.08,10.62 36.95,10.75 36.8,10.9 36.8,14.1 36.5,14.4 36.5,15.85 35.5,16.85 35.15,16.85 34.6,17.4 Q4.5 ; 47.8,8 60.27,8 61.37,9.1 64.55,9.1 v1(65.25,8.4) ; 47.8,8 47.8,10.43 47.55,10.68 47.55,11.94 47.68,12.07 47.68,13.91 47.03,14.55 U4.2 ; v1(65.05,26.32) 64.52,26.32 64.15,26.69 R14.8
  BOTTOM w0.15: v1(65.25,8.4) 65.25,12.59 66.25,13.59 66.25,17.83 64.67,19.41 64.67,20.42 64.53,20.56 64.53,20.98 64.65,21.1 64.65,25.92 v1(65.05,26.32)
/ENABLE_UART_TX_PULLUP_GOPORT2: length 10.8
  TOP w0.15: 63.6,25.55 62.83,25.55 62.13,24.85 61.17,24.85 61,24.68 U4.41 ; 63.6,25.55 65.1,25.55 66.4,26.85 Q8.2 ; 63.6,25.55 R14.7
/ENABLE_UART_TX_PULLUP_GOPORT3: length 12.3
  TOP w0.15: 62.1,26.65 62.1,29.45 63.58,30.93 66.25,30.93 66.4,30.78 Q8.5 ; 62.1,26.65 62.62,26.65 63.1,27.12 R14.6 ; 62.1,26.65 61.13,25.68 U4.43
/EXTERNAL_RESET: length 85.7
  TOP w0.15: v1(47.9,35.55) 47.75,35.4 R4.5 ; v1(42.26,10.45) 42.26,10.97 42.33,11.04 42.33,13.48 v1(42.7,13.85) Q2.5 ; v1(53.85,19.75) v1(50,19.75) 49.3,19.75 47.43,17.88 46.95,17.88 45.02,15.95 v1(44.25,15.95) ; J7.5 69,26.34 69,27 68.4,27.6 68.4,31.6 67.5,32.5 65.24,32.5 64.3,33.44 64.3,35.11 v1(62.33,37.08)
  BOTTOM w0.15: v1(62.33,37.08) 61.18,37.08 60.99,37.26 58.51,37.26 53.65,32.4 53.65,31.99 53.77,31.86 53.77,23.83 53.57,23.63 53.57,22.34 53.6,22.31 53.6,21.89 53.48,21.77 53.48,20.12 v1(53.85,19.75) ; v1(42.7,13.85) 42.7,14.4 v1(44.25,15.95) ; J6.3 42.26,5.43 v1(42.26,10.45) ; v1(50,19.75) 49.63,20.12 49.63,23.18 49.85,23.4 49.85,28.53 48.96,29.43 48.96,32.81 47.9,33.87 v1(47.9,35.55)
/INT_GOPORT1: length 38.9
  TOP w0.15: U4.60 54.03,30.17 54.35,29.85 v1(54.5,29.85) ; J10.3 76.84,11.36 v1(76.7,11.5) ; v1(65.55,13.6) 65.55,12.85 66.7,11.7 74.67,11.7 74.97,11.4 v1(75.5,11.4)
  L2-GND w0.15: v1(54.5,29.85) 55.02,29.85 55.08,29.9 55.45,29.9 57.4,27.95 57.4,26.17 57.9,25.67 57.9,24.3 58.6,23.6 59.8,23.6 61.8,21.6 63.07,21.6 v1(64,20.67)
  BOTTOM w0.15: v1(75.5,11.4) 76.07,11.4 76.17,11.5 v1(76.7,11.5) ; v1(65.55,13.6) 65.95,14 65.95,17.71 64.37,19.29 64.37,20.3 v1(64,20.67)
/INT_GOPORT2: length 33.7
  TOP w0.15: U4.61 53.53,30.02 55,28.55 57.18,28.55 57.33,28.7 v1(57.85,28.7) ; J11.3 77.11,27.94 v1(76.65,28.4)
  L2-GND w0.15: v1(57.85,28.7) 58.22,28.33 59,28.33 62.71,24.62 62.95,24.62 63.24,24.33 63.24,24.32 63.85,23.71 63.85,23.4 65.03,22.22 65.07,22.22 65.17,22.12 66.52,22.12 68.57,24.17 69.48,24.17 69.55,24.1 70.49,24.1 70.64,24.25 71.59,24.25 72.14,23.7 73.72,23.7 76.1,26.08 76.1,27.85 v1(76.65,28.4)
/INT_GOPORT3: length 35.2
  TOP w0.15: v1(53.05,32.2) 53.05,30.95 U4.62 ; J12.3 73.92,44.52 70.9,41.5 70.9,40.52 65.4,35.02 64.9,35.02 62.85,37.08 v1(62.85,37.6)
  BOTTOM w0.15: v1(62.85,37.6) 62.3,37.6 62.15,37.75 58.08,37.75 53.05,32.73 v1(53.05,32.2)
/MICRO_SD_CARD_INSERTED: length 65.9
  TOP w0.15: J9.9 19.1,18.1 v1(19.1,16.8) ; U4.48 55.44,28.18 55.07,27.81 55.07,27.44 54.78,27.15 53.7,27.15 52.65,28.2 49.45,28.2 47.55,30.1 46.05,30.1 45.85,29.9 43.83,29.9 43.2,29.27 43.2,28.87 39.18,24.85 38.73,24.85 37.93,24.05 35.63,24.05 34.8,23.22 34.8,20.03 35.85,18.98 v1(38.45,18.98) 39.3,19.82 39.3,20.35 39,20.65 38.4,20.65 38.08,20.32 R13.4
  BOTTOM w0.15: v1(19.1,16.8) 21.84,16.8 22.19,16.45 23.76,16.45 24.75,15.45 25.75,15.45 26.22,15.92 26.22,16.17 26.22,16.48 26.21,16.49 26.21,16.91 26.5,17.2 27,17.2 27.2,17 32.75,17 33.4,16.35 33.93,16.35 34.8,17.22 34.8,17.75 35.6,18.55 36.75,18.55 37.17,18.98 v1(38.45,18.98)
/MICROSD_CS: length 54.2
  TOP w0.15: v1(26.71,16.7) 26.71,17.14 26.6,17.25 J9.2 ; v1(39.9,17.4) 39.9,15.65 39.65,15.4 39.65,14.05 40.05,13.65 40.05,11.95 43.5,8.5 46.38,8.5 47.15,9.28 v1(47.15,9.8) ; v1(58.88,21.45) 59.25,21.45 59.48,21.68 U4.35
  BOTTOM w0.15: v1(58.88,21.45) 59.25,21.08 59.25,18.75 57.63,17.13 55.05,17.13 54.72,16.8 53.95,16.8 53.6,17.15 50.92,17.15 50.53,16.76 50.53,16.33 49.19,14.99 48.04,14.99 46.68,13.62 46.68,12.47 47.15,12 v1(47.15,9.8) ; v1(26.71,16.7) 32.63,16.7 33.28,16.05 37.3,16.05 38.65,17.4 v1(39.9,17.4)
/PWR_CTRL_GOPORT1: length 15.3
  TOP w0.15: Q5.5 Q5.2 73.1,12.5 72.85,12.25 70.98,12.25 70.75,12.48 Q6.3 70.75,13.95 v1(70.7,14) ; v1(67.02,20.12) 67.02,20.12 67.05,20.09 R12.7
  BOTTOM w0.15: v1(70.7,14) 70.7,14.4 70.57,14.53 70.57,14.74 69.95,15.37 69.95,17.03 69.13,17.85 68.64,17.85 67.65,18.84 67.65,19.5 v1(67.02,20.12)
/PWR_CTRL_GOPORT2: length 14.1
  TOP w0.15: Q6.6 69.45,15.5 70.2,16.25 72.85,16.25 73.1,16.5 Q7.2 Q7.5 73.1,19.52 72.54,20.07 70.93,20.07 70.78,20.23 70.29,20.23 69.97,19.9 67.7,19.9 67.55,19.75 R12.6
/PWR_CTRL_GOPORT3: length 12.9
  TOP w0.15: R12.5 68.1,19.1 68.27,18.93 68.6,18.93 69.88,17.65 70.75,17.65 ; Q9.5 v1(73.1,21.9) Q9.2 ; 70.75,17.65 71.1,18 v1(71.15,18) ; 70.75,17.65 Q10.3
  BOTTOM w0.15: v1(73.1,21.9) 72.57,21.38 72.57,21.07 71.8,20.3 70.41,20.3 70.04,19.93 70.04,19.49 71.15,18.37 v1(71.15,18)
/PWR_CTRL_MICROSD: length 53.2
  TOP w0.15: U4.36 61.11,22.18 v1(62.29,21) ; v1(61.5,5.25) 59.4,7.35 43.38,7.35 40.7,10.03 36.83,10.03 36.7,10.15 36.2,10.65 36.2,13.85 35.25,14.8 R11.8
  TOP w0.18: R11.8 34.7,15.24 34.6,15.34 Q4.2
  BOTTOM w0.15: v1(62.29,21) 61.92,20.63 61.92,20.52 60.68,19.27 60.68,12.62 61.5,11.8 v1(61.5,5.25)
/RESET_MCU: length 57
  TOP w0.15: v1(55.85,9.7) 56.85,10.7 56.85,11.2 57.05,11.4 C53.1 57.55,11.39 57.55,10.85 57.89,10.51 v1(62.34,10.51) ; U4.14 53.03,16.17 52.75,16.45 52.6,16.45 v1(52.52,16.52) ; Q2.6 43.9,14.5 44.1,14.3 44.1,13.03 43.8,12.73 43.8,11.9 43.14,11.24 43.14,10.08 44.17,9.05 46.11,9.05 46.6,9.54 46.6,10 47.18,10.57 47.18,12.23 47.27,12.33 47.27,13.25 v1(47.18,13.35) R5.7
  BOTTOM w0.15: v1(47.18,13.35) 48.51,14.69 50.69,14.69 v1(52.52,16.52) 52.95,16.1 52.95,12.6 v1(55.85,9.7) ; J8.10 61.45,25.35 60.83,24.73 60.83,23.28 62.85,21.26 62.85,20.7 62.35,20.2 62.35,18.92 62.1,18.67 62.1,17.13 62.35,16.88 62.35,15 62.75,14.6 62.75,11.85 62.34,11.44 v1(62.34,10.51)
/SPI_CS_GOPORT1: length 72.5
  TOP w0.15: v1(80.62,9.8) 80.91,10.09 J10.6 ; U4.81 45.63,26.68 45.65,26.7 46.15,26.7 46.59,26.26 46.59,25.85 v1(46.11,25.37)
  BOTTOM w0.15: v1(80.62,9.8) 80.62,4.67 77.76,1.8 71.2,1.8 70.55,1.15 55.8,1.15 51.6,5.35 47.83,5.35 45.24,7.94 45.24,10.19 44.54,10.89 44.34,10.89 43.8,11.42 43.8,11.67 43.8,13.03 43.98,13.2 45.55,14.77 45.55,15.62 42.69,18.48 42.69,18.86 41.78,19.77 41.6,19.95 41.6,21.62 43.23,23.25 43.98,23.25 v1(46.11,25.37)
/SPI_CS_GOPORT2: length 83.9
  TOP w0.15: J11.6 v1(80.65,26.67) ; v1(70.05,5.45) 68.98,4.38 54.75,4.38 54.62,4.5 v1(54.1,4.5) ; v1(45.85,26.2) 45.55,26.2 45.53,26.18 U4.82
  BOTTOM w0.15: v1(80.65,26.67) 80.65,23.4 81.7,22.35 81.7,14.59 82.1,14.19 82.1,12.34 74.84,5.08 70.42,5.08 v1(70.05,5.45) ; v1(54.1,4.5) 53.16,4.5 52.01,5.65 47.95,5.65 45.54,8.06 45.54,10.31 45.18,10.66 44.66,11.19 44.46,11.19 44.1,11.55 44.1,12.9 45.67,14.47 45.85,14.65 45.85,16.89 43.48,19.26 43.24,19.26 42.6,19.9 42.58,19.9 41.9,20.58 41.9,21.5 43.35,22.95 44.39,22.95 46.61,25.17 46.61,25.97 46.38,26.2 v1(45.85,26.2)
/SPI_CS_GOPORT3: length 58.4
  TOP w0.15: J12.6 80.85,43.25 80.2,43.9 80.2,46.5 79.16,47.55 75.49,47.55 69.45,41.5 69.45,39.77 v1(66.09,36.41) ; U4.83 45.46,25.68 45.61,25.53 45.61,25.17 46.22,24.55 49.75,24.55 50.04,24.84 51.64,24.84 52.43,24.05 54.45,24.05 v1(56.05,22.45)
  BOTTOM w0.15: v1(66.09,36.41) 64.89,35.22 61.65,35.22 61.18,34.75 61.18,33.9 59.01,31.73 59.01,31.4 57.84,30.23 57.51,30.23 57.25,29.97 57.25,27.28 56.05,26.08 v1(56.05,22.45)
A0: length 16.9
  TOP w0.15: v1(53.4,16.65) 53.4,16.5 53.53,16.37 U4.15
  BOTTOM w0.15: J4.1 57.15,9.2 53.4,12.95 v1(53.4,16.65)
A1: length 15.2
  TOP w0.15: v1(54.4,13.9) 54.4,14.34 54.03,14.71 U4.16
  BOTTOM w0.15: v1(54.4,13.9) 54.4,12.75 58.7,8.45 58.7,3.53 J4.2
A2: length 16.1
  TOP w0.15: U4.17 54.53,14.77 54.94,14.36 v1(54.96,14.36)
  BOTTOM w0.15: J4.3 59.13,5.64 59.13,8.44 54.96,12.61 v1(54.96,14.36)
A3: length 20.3
  TOP w0.18: v1(55.26,16.63) 55.18,16.55 55.18,16.27 55.03,16.13 U4.18
  BOTTOM w0.15: v1(55.26,16.63) 55.26,15.79 57.3,13.75 57.3,11.15 59.43,9.02 59.43,6.27 61.2,4.5 62.81,4.5 J4.4
A4: length 21.7
  TOP w0.15: v1(62.6,17.7) 62.6,19.08 61.8,19.88 61.8,20.23 61.36,20.68 U4.33
  BOTTOM w0.15: J4.5 63.45,6.4 63.45,14.65 62.79,15.31 62.79,16.99 62.6,17.18 v1(62.6,17.7)
A5: length 23.8
  TOP w0.15: U4.34 61.28,21.18 62.1,20.36 62.1,20 63.23,18.88 63.23,17.87 v1(63.6,17.5)
  BOTTOM w0.15: v1(63.6,17.5) 64.3,16.8 64.3,14.75 63.8,14.25 63.8,8.3 65.05,7.05 65.34,7.05 J4.6
CC_CTS: length 25
  TOP w0.15: U5.51 24.55,26.14 v1(24.55,26.9) ; U4.85 43.08,24.68 42.35,23.95 39.1,23.95 37.92,22.77 37.81,22.77 37.79,22.75 37.38,22.75 37.36,22.77 v1(36.72,22.77)
  BOTTOM w0.15: v1(24.55,26.9) 30.1,21.35 33.4,21.35 34.82,22.77 v1(36.72,22.77)
CC_IRQ: length 46.2
  TOP w0.15: U5.11 30.95,38.62 31.38,39.05 41.3,39.05 42.55,40.3 v1(43.5,40.3) ; v1(49.25,25.06) 49.78,25.06 49.86,25.14 51.76,25.14 52.55,24.35 54.9,24.35 56.95,22.3 56.95,21.31 59.01,19.26 59.01,19.11 59.43,18.68 U4.29
  BOTTOM w0.15: v1(49.25,25.06) 48.66,25.65 48.66,32.69 45.51,35.83 45.51,35.86 45.4,35.97 45.4,38.92 44.11,40.21 43.89,40.21 43.8,40.3 v1(43.5,40.3)
CC_MISO: length 39.7
  TOP w0.15: U5.7 30.3,33.55 v1(29.45,33.55) ; U4.31 59.43,19.68 57.55,21.56 57.55,22.55 55.15,24.95 52.8,24.95 52.01,25.74 49.78,25.74 49.67,25.86 48.82,25.86 v1(47.21,27.46)
  BOTTOM w0.15: v1(29.45,33.55) 28.95,33.05 28.95,31.9 29.2,31.65 29.51,31.65 31.41,29.75 31.68,29.75 32.65,28.77 45.92,28.77 46.76,27.94 46.76,27.93 47.22,27.47 47.22,27.47 47.22,27.47 47.22,27.46 47.22,27.46 v1(47.21,27.46)
CC_MOSI: length 37.2
  TOP w0.15: U4.32 59.42,20.18 57.85,21.75 57.85,22.67 55.27,25.25 52.92,25.25 52.13,26.04 49.91,26.04 49.79,26.16 49.5,26.16 v1(47.56,28.1) ; v1(29.45,32.27) U5.6
  BOTTOM w0.15: v1(29.45,32.27) 31.67,30.05 31.8,30.05 32.77,29.07 46.58,29.07 v1(47.56,28.1)
CC_RTS: length 34.8
  TOP w0.15: U5.44 15.9,26.55 16.2,26.85 v1(17.25,26.85) ; U4.84 43.16,25.18 42.23,24.25 38.98,24.25 37.98,23.25 v1(37.58,23.25)
  BOTTOM w0.15: v1(17.25,26.85) 17.9,26.2 19.75,26.2 22.55,23.4 22.55,23.18 22.55,22.93 25.03,20.45 33.87,20.45 34.62,21.2 35.95,21.2 37.58,22.83 v1(37.58,23.25)
CC_RX: length 30.2
  TOP w0.15: U4.86 43.01,24.18 42.48,23.65 39.23,23.65 37.83,22.25 v1(36.21,22.25) ; U5.47 19.8,25.99 v1(19.8,27)
  BOTTOM w0.15: v1(36.21,22.25) 34.8,22.25 33.6,21.05 25.28,21.05 23.15,23.18 23.15,23.65 v1(19.8,27)
CC_SCK: length 37.7
  TOP w0.15: v1(46.23,27.76) 46.61,27.39 46.61,27.21 48.27,25.56 49.54,25.56 49.66,25.44 51.88,25.44 52.68,24.65 55.02,24.65 57.25,22.42 57.25,21.44 59.31,19.38 59.31,19.31 59.43,19.18 U4.30 ; v1(29.45,31) 30.3,31
  BOTTOM w0.15: v1(29.45,31) 29.45,30.25 31.22,28.48 45.52,28.48 v1(46.23,27.76)
CC_TCXO_EN/SOP2: length 73.4
  TOP w0.15: U4.46 59.43,27.18 59.16,27.45 57.84,27.45 57.24,26.85 53.58,26.85 52.53,27.9 49.32,27.9 47.62,29.6 v1(46.35,29.6) 43.95,29.6 43.5,29.15 43.5,28.75 39.3,24.55 38.85,24.55 38.05,23.75 35.76,23.75 35.1,23.09 35.1,20.15 35.55,19.7 35.6,19.7 35.62,19.68 R13.2 ; U5.23 20.98,45.73 21.5,46.25 22.14,46.25 22.39,46.5 23.82,46.5 24.52,47.2 36.19,47.2 37.94,45.45 v1(38.7,45.45)
  BOTTOM w0.15: v1(46.35,29.6) 46.35,31.46 44.7,33.11 44.7,33.5 41.95,36.25 41.95,43.45 39.95,45.45 v1(38.7,45.45)
CC_TX: length 31.3
  TOP w0.15: U5.46 18.44,26.54 v1(18.95,27.05) ; v1(35.67,21.75) 36.57,21.75 36.58,21.75 37.75,21.75 37.93,21.93 39.35,23.35 42.6,23.35 42.93,23.68 U4.87
  BOTTOM w0.15: v1(35.67,21.75) 34.75,21.75 33.75,20.75 25.15,20.75 22.85,23.05 22.85,23.53 19.88,26.5 19.5,26.5 v1(18.95,27.05)
D0: length 31.1
  TOP w0.15: v1(65.27,47.9) 61.63,47.9 53.1,39.37 53.1,33.38 52.03,32.31 U4.64
  BOTTOM w0.15: J2.1 69.85,49.55 69.2,48.9 66.27,48.9 v1(65.27,47.9)
D1: length 29.2
  TOP w0.15: U4.63 52.53,32.39 53.4,33.26 53.4,39.25 61.25,47.1 66.7,47.1 67.31,47.71 J2.2
D2: length 42.9
  TOP w0.15: v1(58.3,19.26) 58.85,18.7 58.85,17.97 59.64,17.18 U4.26
  BOTTOM w0.15: J2.3 64.77,49.55 63.95,48.73 63.95,37.14 62.62,35.82 61.4,35.82 60.58,35 60.58,34.75 60.58,34.15 58.41,31.98 58.41,31.65 57.59,30.83 57.26,30.83 56.65,30.22 56.65,27.53 54.87,25.75 54.87,20.23 56.05,19.05 57.55,19.05 57.76,19.26 v1(58.3,19.26)
D3: length 42.7
  TOP w0.15: U4.25 58.53,16.13 56.46,18.21 v1(55.78,18.21)
  BOTTOM w0.15: v1(55.78,18.21) 54.57,19.41 54.57,25.88 56.35,27.65 56.35,30.34 57.13,31.13 57.47,31.13 58.11,31.77 58.11,32.13 60.28,34.3 60.28,35.12 61.28,36.12 62.5,36.12 63.65,37.27 63.65,49.38 J2.4
D4: length 22.3
  TOP w0.15: U4.51 58.53,41.7 v1(60.24,43.41)
  BOTTOM w0.15: J2.5 62,48.49 62,45.17 v1(60.24,43.41)
D5: length 40.9
  TOP w0.15: U4.95 47.53,19.68 49.95,22.1 v1(53.1,22.1) ; v1(55.25,47.35) 55.25,48.9 J2.6
  BOTTOM w0.15: v1(53.1,22.1) 53.27,22.27 53.27,23.75 53.45,23.93 53.45,23.93 53.47,23.95 53.47,28.7 53.45,28.72 53.45,31.09 52.55,31.99 52.55,41.07 52.05,41.57 52.05,44.15 v1(55.25,47.35)
D6: length 41.3
  TOP w0.15: v1(52.1,21.55) 51.58,21.55 51.43,21.7 49.98,21.7 47.46,19.18 U4.96 ; v1(51.6,33.95) 49.8,35.75 49.8,38.98 54.61,43.79 J2.7
  BOTTOM w0.15: v1(51.6,33.95) 51.6,32.09 52.85,30.84 52.85,28.47 52.87,28.45 52.87,24.2 52.67,24 52.67,22.8 52.1,22.23 v1(52.1,21.55)
D7: length 40.6
  TOP w0.15: v1(55.07,18.05) 55.44,17.68 56.27,17.68 57.02,16.93 57.31,16.93 58.03,16.21 U4.24 ; v1(50.26,44.1) 50.26,48.99 J2.8
  BOTTOM w0.15: v1(55.07,18.05) 54.52,18.6 54.29,18.6 52.65,20.24 52.65,21.71 52.55,21.81 52.55,22.26 52.97,22.68 52.97,23.88 53.17,24.08 53.17,28.57 53.15,28.59 53.15,30.97 52.25,31.87 52.25,40.95 50.26,42.94 v1(50.26,44.1)
D8: length 41.7
  TOP w0.15: v1(49.53,44.1) 49.53,45.82 48.01,47.34 J3.1 ; U4.23 57.53,16.28 57.18,16.63 56.62,16.63 56.02,17.23 54.85,17.23 v1(54.43,17.64)
  BOTTOM w0.15: v1(54.43,17.64) 51.6,20.48 51.6,22.16 52.37,22.93 52.37,24.13 52.57,24.33 52.57,28.32 52.55,28.35 52.55,30.72 51.1,32.17 51.1,34.16 51.8,34.86 51.8,40.25 49.53,42.52 v1(49.53,44.1)
D9: length 41.1
  TOP w0.15: U4.4 48.03,16.38 49.55,17.9 v1(50.5,17.9) ; v1(48.81,44.1) 48.81,45.84 45.47,49.18 J3.2
  BOTTOM w0.15: v1(50.5,17.9) 51.3,18.7 51.3,19.58 51.3,22.28 52.07,23.05 52.07,24.25 52.27,24.45 52.27,28.2 52.25,28.22 52.25,30.6 50.8,32.05 50.8,34.28 51.5,34.98 51.5,40.13 48.81,42.82 v1(48.81,44.1)
D10: length 45.8
  TOP w0.15: v1(55.65,27.68) 56.87,27.68 56.94,27.75 59.35,27.75 59.42,27.68 U4.47 ; v1(52.55,43.55) 48.55,43.55 42.93,49.17 J3.3
  BOTTOM w0.15: v1(52.55,43.55) 56,40.1 61.2,40.1 63.35,37.95 63.35,37.39 62.38,36.42 61.15,36.42 59.98,35.25 59.98,34.42 57.81,32.25 57.81,31.9 57.34,31.43 56.99,31.43 56.05,30.49 56.05,28.61 55.65,28.21 v1(55.65,27.68)
D11: length 64.6
  TOP w0.15: v1(66,37.65) 65.63,38.02 65.38,38.02 61.45,41.96 v1(61.45,46.47) 57.8,42.81 57.8,32.12 57.5,31.83 57.13,31.83 57.03,31.73 U4.54
  BOTTOM w0.15: J7.4 71.28,29.14 71.28,30.95 71.7,31.37 71.7,32.85 68.3,36.25 68.14,36.25 66.74,37.65 v1(66,37.65) ; v1(61.45,46.47) 58.67,49.25 41.94,49.25 J3.4
D12: length 56.1
  TOP w0.15: v1(63.05,34.32) 63.05,33.63 62.32,32.9 60.92,32.9 59.46,31.44 59.46,30.11 59.05,29.7 57.91,29.7 57.53,30.08 U4.53 ; v1(62.04,34.33) 61.67,34.7 61.67,34.73 59.35,37.05 59.35,37.43 59.35,41.8 v1(60.1,42.55)
  BOTTOM w0.15: J3.5 39.7,48.95 55.12,48.95 56.7,47.37 56.7,45.95 v1(60.1,42.55) ; v1(62.04,34.33) 62.52,34.33 62.53,34.32 v1(63.05,34.32) 63.66,34.32 63.7,34.28 67.41,34.28 69.99,31.7 J7.1
D13: length 59.1
  TOP w0.15: v1(60.6,42) 60.6,40.2 60.2,39.8 60.2,36.62 61.42,35.4 61.8,35.4 62.55,34.65 62.55,33.9 v1(62.3,33.65) 61.85,33.2 60.8,33.2 59.16,31.56 59.16,30.26 58.9,30 58.29,30 58.03,30.26 U4.52
  BOTTOM w0.15: v1(62.3,33.65) 64.4,33.65 64.73,33.98 66.37,33.98 68.39,31.95 68.39,29.29 68.85,28.84 69.05,28.84 J7.3 ; J3.6 36.81,49.3 38.92,49.3 39.57,48.65 55,48.65 56.35,47.3 56.35,45.45 59.8,42 v1(60.6,42)
JTCK: length 20.3
  TOP w0.15: U4.76 46.06,29.18 46.19,29.05 47.75,29.05 49.2,27.6 52.4,27.6 53.45,26.55 57.86,26.55 v1(58.23,26.92)
  BOTTOM w0.15: v1(58.23,26.92) 60.47,29.16 J8.4
JTDI: length 20.2
  TOP w0.15: v1(56.81,25.18) 56.29,25.18 55.91,25.55 53.05,25.55 52.26,26.34 50.03,26.34 47.69,28.68 U4.77
  BOTTOM w0.15: J8.8 60.42,26.62 59.25,25.45 58.64,25.45 58.37,25.18 v1(56.81,25.18)
JTDO: length 22.5
  TOP w0.15: v1(51.3,24.04) 50.78,24.04 50.69,23.96 50.08,23.96 50.08,23.95 47.78,23.95 46.5,22.68 U4.89 ; v1(51.77,26.84) 52.46,26.84 53.4,25.9 v1(56.75,25.9)
  BOTTOM w0.15: v1(56.75,25.9) 57.8,25.9 57.9,25.8 59.15,25.8 61.24,27.89 J8.6 ; v1(51.77,26.84) 51.77,25.67 51.3,25.2 v1(51.3,24.04)
